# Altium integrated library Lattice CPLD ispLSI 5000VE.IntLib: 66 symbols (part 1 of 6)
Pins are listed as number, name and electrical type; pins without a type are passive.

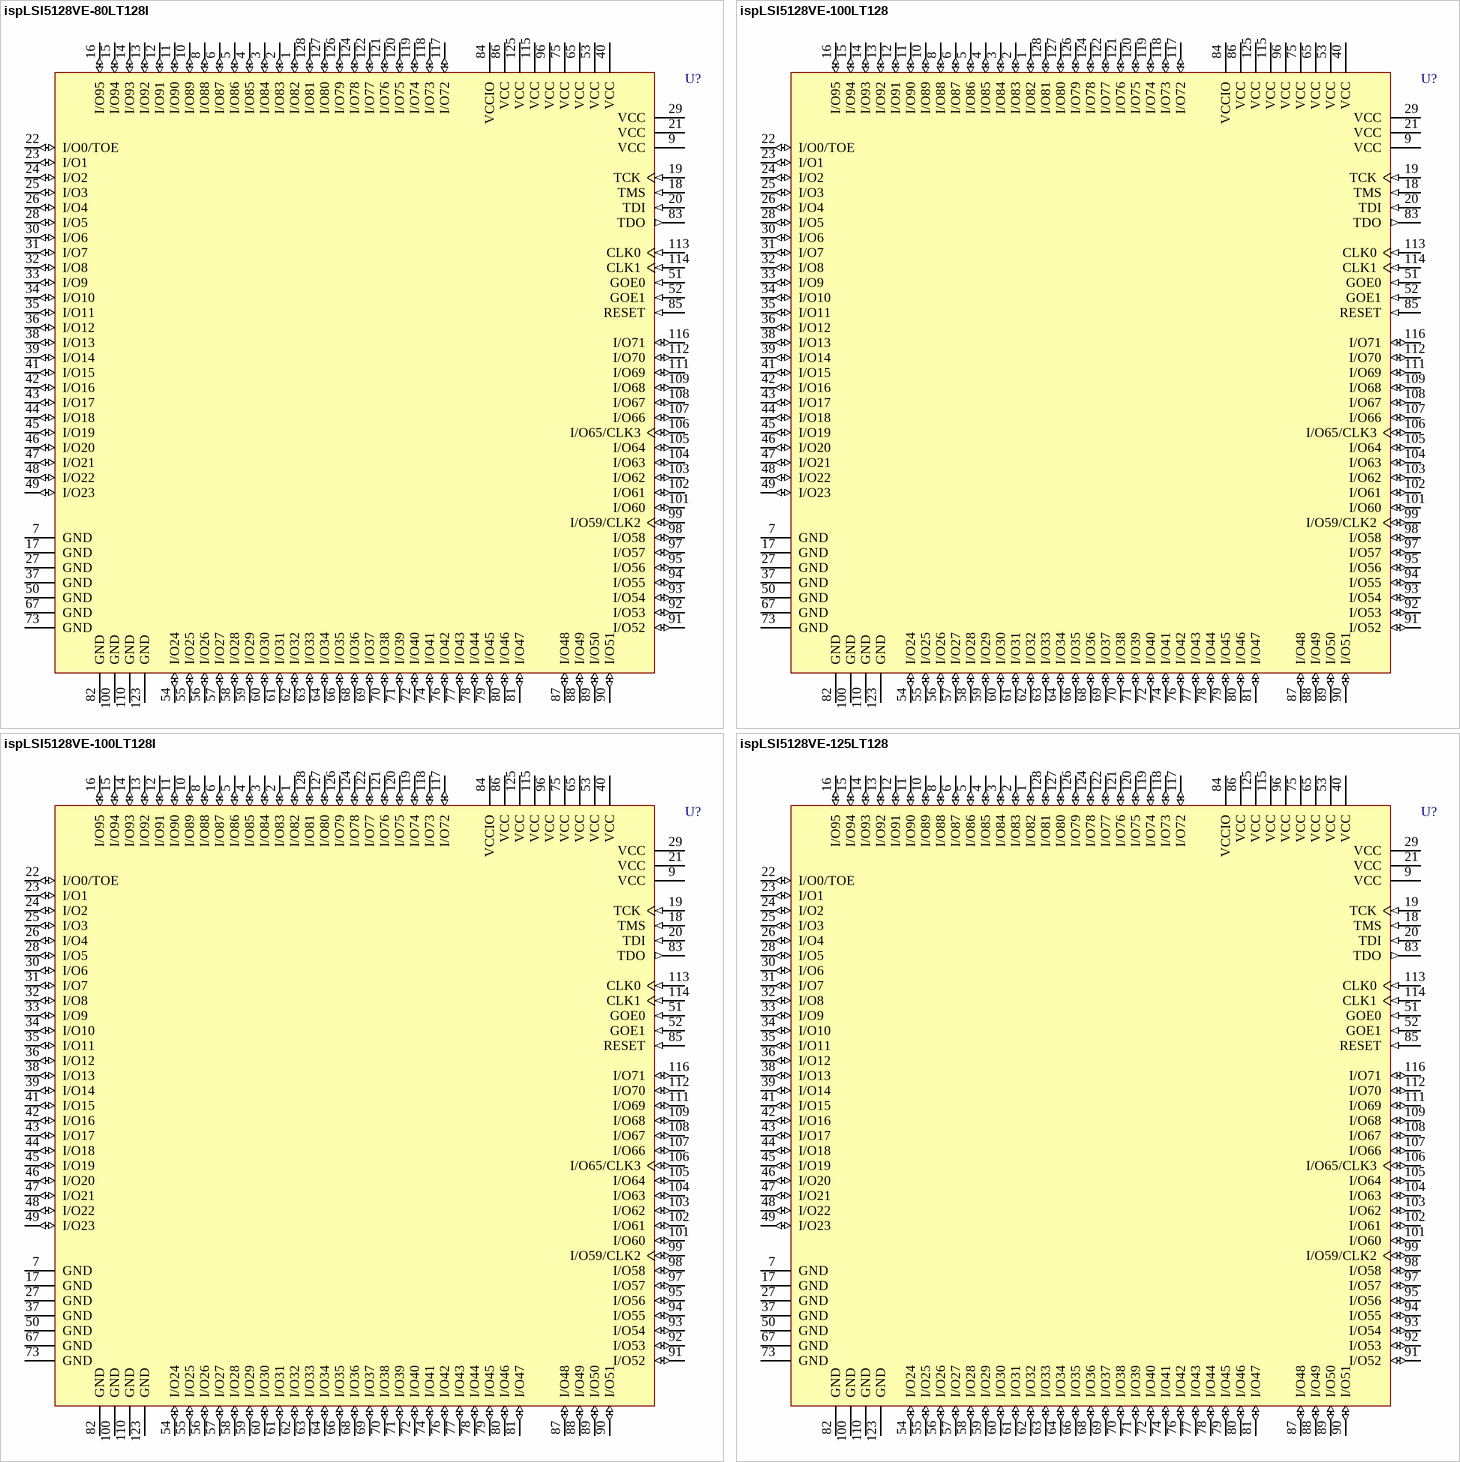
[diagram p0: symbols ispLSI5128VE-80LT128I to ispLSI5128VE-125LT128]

## ispLSI5128VE-80LT128I
designator U?
ispLSI 5128VE SuperWIDE High Density PLD with 96 User I/Os, 12 ns, 3.3 V, Industrial Grade
footprint TQFP128_N (Thin QFP, 128-Leads, Body 14x14mm, Pitch 0.4mm, IPC Medium Density)
footprint TQFP128_L (Thin QFP, 128-Leads, Body 14x14mm, Pitch 0.4mm, IPC High Density)
footprint TQFP128_M (Thin QFP, 128-Leads, Body 14x14mm, Pitch 0.4mm, IPC Low Density)
3D model 5128VE-TQFP128 (128-Pin Thin Quad Flat Pack 0.4 mm Pitch)
pins: 1 I/O82 (io), 2 I/O83 (io), 3 I/O84 (io), 4 I/O85 (io), 5 I/O86 (io), 6 I/O87 (io), 7 GND (power), 8 I/O88 (io), 9 VCC (power), 10 I/O89 (io), 11 I/O90 (io), 12 I/O91 (io), 13 I/O92 (io), 14 I/O93 (io), 15 I/O94 (io), 16 I/O95 (io), 17 GND (power), 18 TMS (in), 19 TCK (in), 20 TDI (in), 21 VCC (power), 22 I/O0/TOE (io), 23 I/O1 (io), 24 I/O2 (io), 25 I/O3 (io), 26 I/O4 (io), 27 GND (power), 28 I/O5 (io), 29 VCC (power), 30 I/O6 (io), 31 I/O7 (io), 32 I/O8 (io), 33 I/O9 (io), 34 I/O10 (io), 35 I/O11 (io), 36 I/O12 (io), 37 GND (power), 38 I/O13 (io), 39 I/O14 (io), 40 VCC (power), 41 I/O15 (io), 42 I/O16 (io), 43 I/O17 (io), 44 I/O18 (io), 45 I/O19 (io), 46 I/O20 (io), 47 I/O21 (io), 48 I/O22 (io), 49 I/O23 (io), 50 GND (power), 51 GOE0 (in), 52 GOE1 (in), 53 VCC (power), 54 I/O24 (io), 55 I/O25 (io), 56 I/O26 (io), 57 I/O27 (io), 58 I/O28 (io), 59 I/O29 (io), 60 I/O30 (io), 61 I/O31 (io), 62 I/O32 (io), 63 I/O33 (io), 64 I/O34 (io), 65 VCC (power), 66 I/O35 (io), 67 GND (power), 68 I/O36 (io), 69 I/O37 (io), 70 I/O38 (io), 71 I/O39 (io), 72 I/O40 (io), 73 GND (power), 74 I/O41 (io), 75 VCC (power), 76 I/O42 (io), 77 I/O43 (io), 78 I/O44 (io), 79 I/O45 (io), 80 I/O46 (io), 81 I/O47 (io), 82 GND (power), 83 TDO (out), 84 VCCIO (power), 85 RESET (in), 86 VCC (power), 87 I/O48 (io), 88 I/O49 (io), 89 I/O50 (io), 90 I/O51 (io), 91 I/O52 (io), 92 I/O53 (io), 93 I/O54 (io), 94 I/O55 (io), 95 I/O56 (io), 96 VCC (power), 97 I/O57 (io), 98 I/O58 (io), 99 I/O59/CLK2 (io), 100 GND (power), 101 I/O60 (io), 102 I/O61 (io), 103 I/O62 (io), 104 I/O63 (io), 105 I/O64 (io), 106 I/O65/CLK3 (io), 107 I/O66 (io), 108 I/O67 (io), 109 I/O68 (io), 110 GND (power), 111 I/O69 (io), 112 I/O70 (io), 113 CLK0 (in), 114 CLK1 (in), 115 VCC (power), 116 I/O71 (io), 117 I/O72 (io), 118 I/O73 (io), 119 I/O74 (io), 120 I/O75 (io), 121 I/O76 (io), 122 I/O77 (io), 123 GND (power), 124 I/O78 (io), 125 VCC (power), 126 I/O79 (io), 127 I/O80 (io), 128 I/O81 (io)

## ispLSI5128VE-100LT128
designator U?
ispLSI 5128VE SuperWIDE High Density PLD with 96 User I/Os, 10 ns, 3.3 V, Commercial Grade
footprint TQFP128_N (Thin QFP, 128-Leads, Body 14x14mm, Pitch 0.4mm, IPC Medium Density)
footprint TQFP128_L (Thin QFP, 128-Leads, Body 14x14mm, Pitch 0.4mm, IPC High Density)
footprint TQFP128_M (Thin QFP, 128-Leads, Body 14x14mm, Pitch 0.4mm, IPC Low Density)
3D model 5128VE-TQFP128 (128-Pin Thin Quad Flat Pack 0.4 mm Pitch)
pins: 1 I/O82 (io), 2 I/O83 (io), 3 I/O84 (io), 4 I/O85 (io), 5 I/O86 (io), 6 I/O87 (io), 7 GND (power), 8 I/O88 (io), 9 VCC (power), 10 I/O89 (io), 11 I/O90 (io), 12 I/O91 (io), 13 I/O92 (io), 14 I/O93 (io), 15 I/O94 (io), 16 I/O95 (io), 17 GND (power), 18 TMS (in), 19 TCK (in), 20 TDI (in), 21 VCC (power), 22 I/O0/TOE (io), 23 I/O1 (io), 24 I/O2 (io), 25 I/O3 (io), 26 I/O4 (io), 27 GND (power), 28 I/O5 (io), 29 VCC (power), 30 I/O6 (io), 31 I/O7 (io), 32 I/O8 (io), 33 I/O9 (io), 34 I/O10 (io), 35 I/O11 (io), 36 I/O12 (io), 37 GND (power), 38 I/O13 (io), 39 I/O14 (io), 40 VCC (power), 41 I/O15 (io), 42 I/O16 (io), 43 I/O17 (io), 44 I/O18 (io), 45 I/O19 (io), 46 I/O20 (io), 47 I/O21 (io), 48 I/O22 (io), 49 I/O23 (io), 50 GND (power), 51 GOE0 (in), 52 GOE1 (in), 53 VCC (power), 54 I/O24 (io), 55 I/O25 (io), 56 I/O26 (io), 57 I/O27 (io), 58 I/O28 (io), 59 I/O29 (io), 60 I/O30 (io), 61 I/O31 (io), 62 I/O32 (io), 63 I/O33 (io), 64 I/O34 (io), 65 VCC (power), 66 I/O35 (io), 67 GND (power), 68 I/O36 (io), 69 I/O37 (io), 70 I/O38 (io), 71 I/O39 (io), 72 I/O40 (io), 73 GND (power), 74 I/O41 (io), 75 VCC (power), 76 I/O42 (io), 77 I/O43 (io), 78 I/O44 (io), 79 I/O45 (io), 80 I/O46 (io), 81 I/O47 (io), 82 GND (power), 83 TDO (out), 84 VCCIO (power), 85 RESET (in), 86 VCC (power), 87 I/O48 (io), 88 I/O49 (io), 89 I/O50 (io), 90 I/O51 (io), 91 I/O52 (io), 92 I/O53 (io), 93 I/O54 (io), 94 I/O55 (io), 95 I/O56 (io), 96 VCC (power), 97 I/O57 (io), 98 I/O58 (io), 99 I/O59/CLK2 (io), 100 GND (power), 101 I/O60 (io), 102 I/O61 (io), 103 I/O62 (io), 104 I/O63 (io), 105 I/O64 (io), 106 I/O65/CLK3 (io), 107 I/O66 (io), 108 I/O67 (io), 109 I/O68 (io), 110 GND (power), 111 I/O69 (io), 112 I/O70 (io), 113 CLK0 (in), 114 CLK1 (in), 115 VCC (power), 116 I/O71 (io), 117 I/O72 (io), 118 I/O73 (io), 119 I/O74 (io), 120 I/O75 (io), 121 I/O76 (io), 122 I/O77 (io), 123 GND (power), 124 I/O78 (io), 125 VCC (power), 126 I/O79 (io), 127 I/O80 (io), 128 I/O81 (io)

## ispLSI5128VE-100LT128I
designator U?
ispLSI 5128VE SuperWIDE High Density PLD with 96 User I/Os, 10 ns, 3.3 V, Industrial Grade
footprint TQFP128_N (Thin QFP, 128-Leads, Body 14x14mm, Pitch 0.4mm, IPC Medium Density)
footprint TQFP128_L (Thin QFP, 128-Leads, Body 14x14mm, Pitch 0.4mm, IPC High Density)
footprint TQFP128_M (Thin QFP, 128-Leads, Body 14x14mm, Pitch 0.4mm, IPC Low Density)
3D model 5128VE-TQFP128 (128-Pin Thin Quad Flat Pack 0.4 mm Pitch)
pins: 1 I/O82 (io), 2 I/O83 (io), 3 I/O84 (io), 4 I/O85 (io), 5 I/O86 (io), 6 I/O87 (io), 7 GND (power), 8 I/O88 (io), 9 VCC (power), 10 I/O89 (io), 11 I/O90 (io), 12 I/O91 (io), 13 I/O92 (io), 14 I/O93 (io), 15 I/O94 (io), 16 I/O95 (io), 17 GND (power), 18 TMS (in), 19 TCK (in), 20 TDI (in), 21 VCC (power), 22 I/O0/TOE (io), 23 I/O1 (io), 24 I/O2 (io), 25 I/O3 (io), 26 I/O4 (io), 27 GND (power), 28 I/O5 (io), 29 VCC (power), 30 I/O6 (io), 31 I/O7 (io), 32 I/O8 (io), 33 I/O9 (io), 34 I/O10 (io), 35 I/O11 (io), 36 I/O12 (io), 37 GND (power), 38 I/O13 (io), 39 I/O14 (io), 40 VCC (power), 41 I/O15 (io), 42 I/O16 (io), 43 I/O17 (io), 44 I/O18 (io), 45 I/O19 (io), 46 I/O20 (io), 47 I/O21 (io), 48 I/O22 (io), 49 I/O23 (io), 50 GND (power), 51 GOE0 (in), 52 GOE1 (in), 53 VCC (power), 54 I/O24 (io), 55 I/O25 (io), 56 I/O26 (io), 57 I/O27 (io), 58 I/O28 (io), 59 I/O29 (io), 60 I/O30 (io), 61 I/O31 (io), 62 I/O32 (io), 63 I/O33 (io), 64 I/O34 (io), 65 VCC (power), 66 I/O35 (io), 67 GND (power), 68 I/O36 (io), 69 I/O37 (io), 70 I/O38 (io), 71 I/O39 (io), 72 I/O40 (io), 73 GND (power), 74 I/O41 (io), 75 VCC (power), 76 I/O42 (io), 77 I/O43 (io), 78 I/O44 (io), 79 I/O45 (io), 80 I/O46 (io), 81 I/O47 (io), 82 GND (power), 83 TDO (out), 84 VCCIO (power), 85 RESET (in), 86 VCC (power), 87 I/O48 (io), 88 I/O49 (io), 89 I/O50 (io), 90 I/O51 (io), 91 I/O52 (io), 92 I/O53 (io), 93 I/O54 (io), 94 I/O55 (io), 95 I/O56 (io), 96 VCC (power), 97 I/O57 (io), 98 I/O58 (io), 99 I/O59/CLK2 (io), 100 GND (power), 101 I/O60 (io), 102 I/O61 (io), 103 I/O62 (io), 104 I/O63 (io), 105 I/O64 (io), 106 I/O65/CLK3 (io), 107 I/O66 (io), 108 I/O67 (io), 109 I/O68 (io), 110 GND (power), 111 I/O69 (io), 112 I/O70 (io), 113 CLK0 (in), 114 CLK1 (in), 115 VCC (power), 116 I/O71 (io), 117 I/O72 (io), 118 I/O73 (io), 119 I/O74 (io), 120 I/O75 (io), 121 I/O76 (io), 122 I/O77 (io), 123 GND (power), 124 I/O78 (io), 125 VCC (power), 126 I/O79 (io), 127 I/O80 (io), 128 I/O81 (io)

## ispLSI5128VE-125LT128
designator U?
ispLSI 5128VE SuperWIDE High Density PLD with 96 User I/Os, 7.5 ns, 3.3 V, Commercial Grade
footprint TQFP128_N (Thin QFP, 128-Leads, Body 14x14mm, Pitch 0.4mm, IPC Medium Density)
footprint TQFP128_L (Thin QFP, 128-Leads, Body 14x14mm, Pitch 0.4mm, IPC High Density)
footprint TQFP128_M (Thin QFP, 128-Leads, Body 14x14mm, Pitch 0.4mm, IPC Low Density)
3D model 5128VE-TQFP128 (128-Pin Thin Quad Flat Pack 0.4 mm Pitch)
pins: 1 I/O82 (io), 2 I/O83 (io), 3 I/O84 (io), 4 I/O85 (io), 5 I/O86 (io), 6 I/O87 (io), 7 GND (power), 8 I/O88 (io), 9 VCC (power), 10 I/O89 (io), 11 I/O90 (io), 12 I/O91 (io), 13 I/O92 (io), 14 I/O93 (io), 15 I/O94 (io), 16 I/O95 (io), 17 GND (power), 18 TMS (in), 19 TCK (in), 20 TDI (in), 21 VCC (power), 22 I/O0/TOE (io), 23 I/O1 (io), 24 I/O2 (io), 25 I/O3 (io), 26 I/O4 (io), 27 GND (power), 28 I/O5 (io), 29 VCC (power), 30 I/O6 (io), 31 I/O7 (io), 32 I/O8 (io), 33 I/O9 (io), 34 I/O10 (io), 35 I/O11 (io), 36 I/O12 (io), 37 GND (power), 38 I/O13 (io), 39 I/O14 (io), 40 VCC (power), 41 I/O15 (io), 42 I/O16 (io), 43 I/O17 (io), 44 I/O18 (io), 45 I/O19 (io), 46 I/O20 (io), 47 I/O21 (io), 48 I/O22 (io), 49 I/O23 (io), 50 GND (power), 51 GOE0 (in), 52 GOE1 (in), 53 VCC (power), 54 I/O24 (io), 55 I/O25 (io), 56 I/O26 (io), 57 I/O27 (io), 58 I/O28 (io), 59 I/O29 (io), 60 I/O30 (io), 61 I/O31 (io), 62 I/O32 (io), 63 I/O33 (io), 64 I/O34 (io), 65 VCC (power), 66 I/O35 (io), 67 GND (power), 68 I/O36 (io), 69 I/O37 (io), 70 I/O38 (io), 71 I/O39 (io), 72 I/O40 (io), 73 GND (power), 74 I/O41 (io), 75 VCC (power), 76 I/O42 (io), 77 I/O43 (io), 78 I/O44 (io), 79 I/O45 (io), 80 I/O46 (io), 81 I/O47 (io), 82 GND (power), 83 TDO (out), 84 VCCIO (power), 85 RESET (in), 86 VCC (power), 87 I/O48 (io), 88 I/O49 (io), 89 I/O50 (io), 90 I/O51 (io), 91 I/O52 (io), 92 I/O53 (io), 93 I/O54 (io), 94 I/O55 (io), 95 I/O56 (io), 96 VCC (power), 97 I/O57 (io), 98 I/O58 (io), 99 I/O59/CLK2 (io), 100 GND (power), 101 I/O60 (io), 102 I/O61 (io), 103 I/O62 (io), 104 I/O63 (io), 105 I/O64 (io), 106 I/O65/CLK3 (io), 107 I/O66 (io), 108 I/O67 (io), 109 I/O68 (io), 110 GND (power), 111 I/O69 (io), 112 I/O70 (io), 113 CLK0 (in), 114 CLK1 (in), 115 VCC (power), 116 I/O71 (io), 117 I/O72 (io), 118 I/O73 (io), 119 I/O74 (io), 120 I/O75 (io), 121 I/O76 (io), 122 I/O77 (io), 123 GND (power), 124 I/O78 (io), 125 VCC (power), 126 I/O79 (io), 127 I/O80 (io), 128 I/O81 (io)

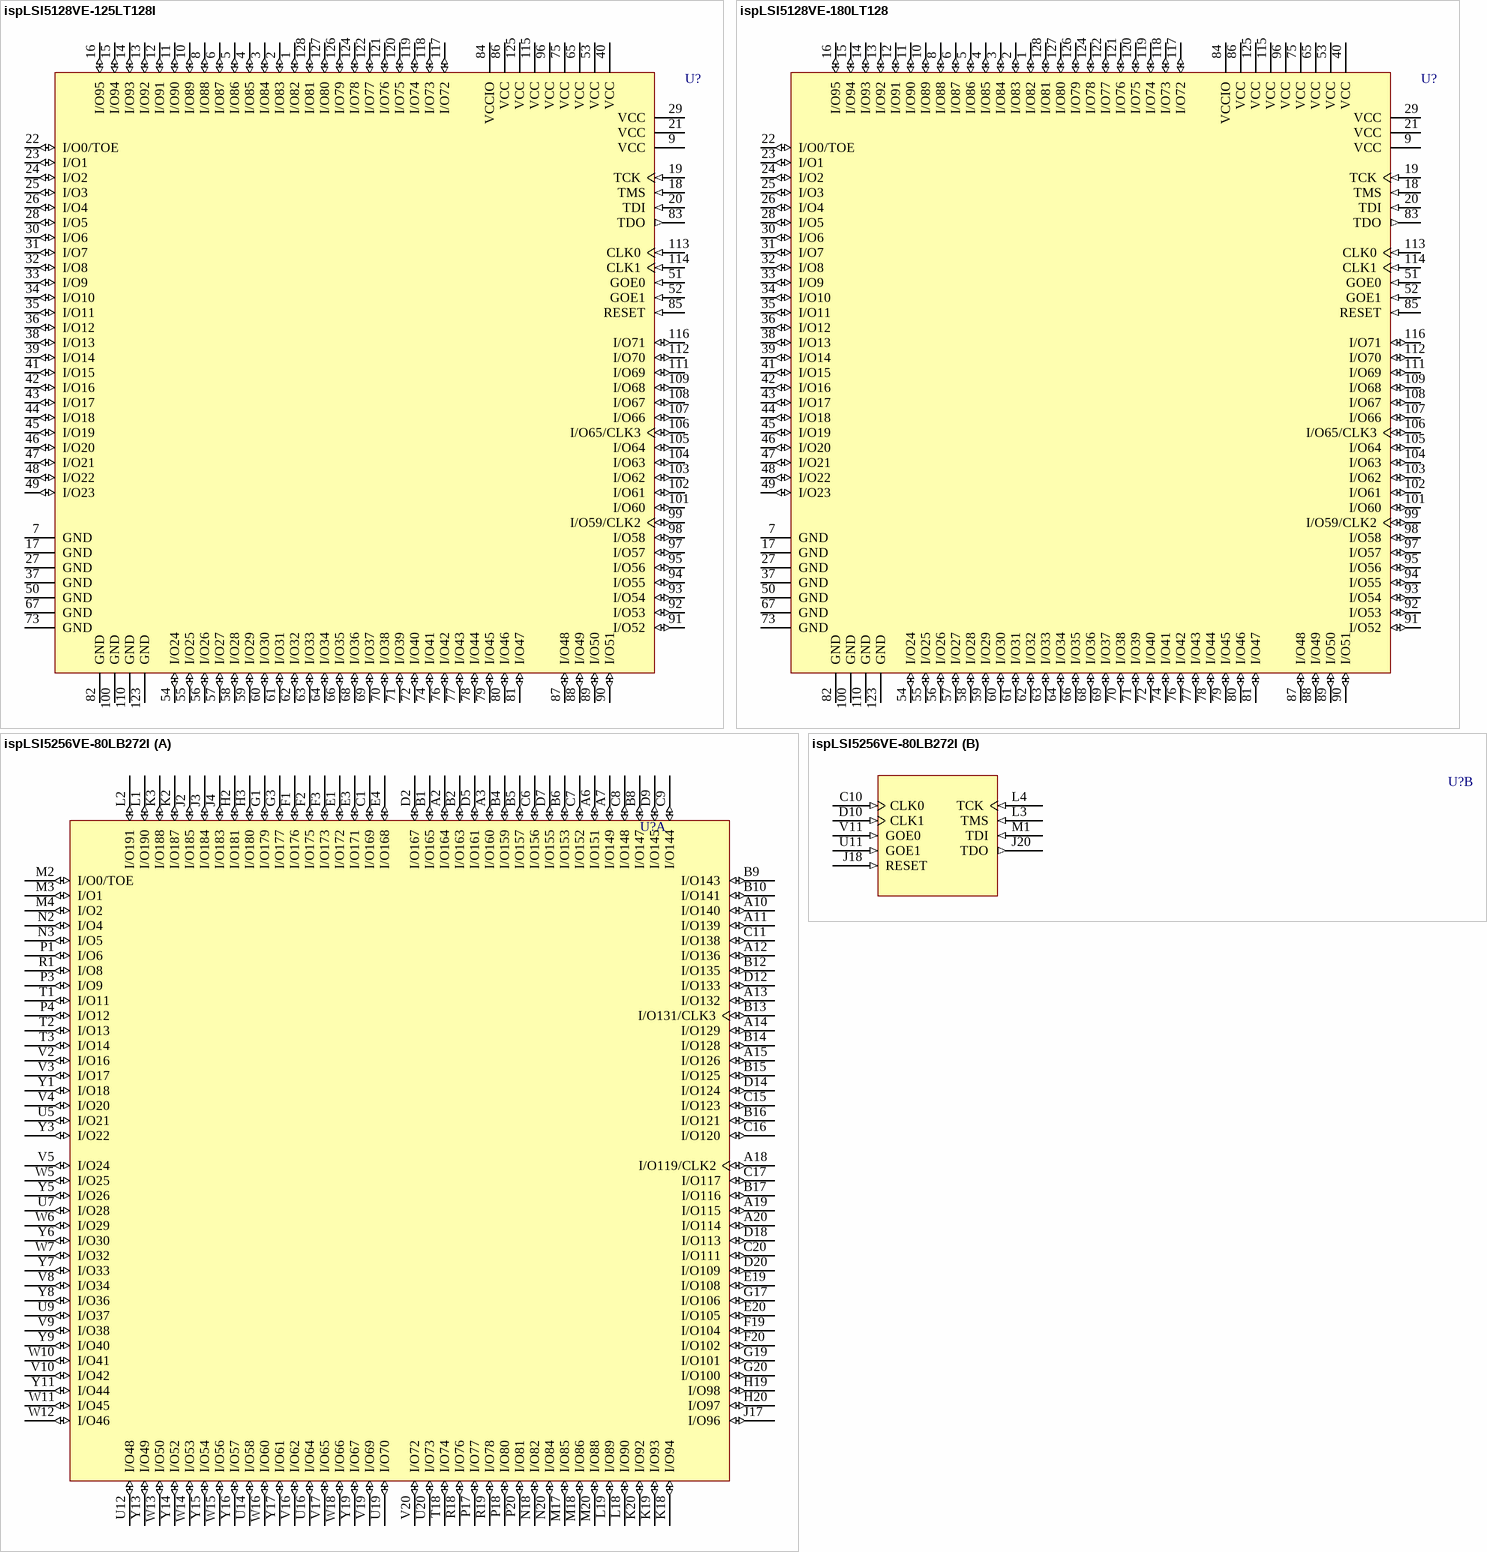
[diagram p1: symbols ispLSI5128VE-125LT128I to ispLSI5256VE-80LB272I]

## ispLSI5128VE-125LT128I
designator U?
ispLSI 5128VE SuperWIDE High Density PLD with 96 User I/Os, 7.5 ns, 3.3 V, Industrial Grade
footprint TQFP128_N (Thin QFP, 128-Leads, Body 14x14mm, Pitch 0.4mm, IPC Medium Density)
footprint TQFP128_L (Thin QFP, 128-Leads, Body 14x14mm, Pitch 0.4mm, IPC High Density)
footprint TQFP128_M (Thin QFP, 128-Leads, Body 14x14mm, Pitch 0.4mm, IPC Low Density)
3D model 5128VE-TQFP128 (128-Pin Thin Quad Flat Pack 0.4 mm Pitch)
pins: 1 I/O82 (io), 2 I/O83 (io), 3 I/O84 (io), 4 I/O85 (io), 5 I/O86 (io), 6 I/O87 (io), 7 GND (power), 8 I/O88 (io), 9 VCC (power), 10 I/O89 (io), 11 I/O90 (io), 12 I/O91 (io), 13 I/O92 (io), 14 I/O93 (io), 15 I/O94 (io), 16 I/O95 (io), 17 GND (power), 18 TMS (in), 19 TCK (in), 20 TDI (in), 21 VCC (power), 22 I/O0/TOE (io), 23 I/O1 (io), 24 I/O2 (io), 25 I/O3 (io), 26 I/O4 (io), 27 GND (power), 28 I/O5 (io), 29 VCC (power), 30 I/O6 (io), 31 I/O7 (io), 32 I/O8 (io), 33 I/O9 (io), 34 I/O10 (io), 35 I/O11 (io), 36 I/O12 (io), 37 GND (power), 38 I/O13 (io), 39 I/O14 (io), 40 VCC (power), 41 I/O15 (io), 42 I/O16 (io), 43 I/O17 (io), 44 I/O18 (io), 45 I/O19 (io), 46 I/O20 (io), 47 I/O21 (io), 48 I/O22 (io), 49 I/O23 (io), 50 GND (power), 51 GOE0 (in), 52 GOE1 (in), 53 VCC (power), 54 I/O24 (io), 55 I/O25 (io), 56 I/O26 (io), 57 I/O27 (io), 58 I/O28 (io), 59 I/O29 (io), 60 I/O30 (io), 61 I/O31 (io), 62 I/O32 (io), 63 I/O33 (io), 64 I/O34 (io), 65 VCC (power), 66 I/O35 (io), 67 GND (power), 68 I/O36 (io), 69 I/O37 (io), 70 I/O38 (io), 71 I/O39 (io), 72 I/O40 (io), 73 GND (power), 74 I/O41 (io), 75 VCC (power), 76 I/O42 (io), 77 I/O43 (io), 78 I/O44 (io), 79 I/O45 (io), 80 I/O46 (io), 81 I/O47 (io), 82 GND (power), 83 TDO (out), 84 VCCIO (power), 85 RESET (in), 86 VCC (power), 87 I/O48 (io), 88 I/O49 (io), 89 I/O50 (io), 90 I/O51 (io), 91 I/O52 (io), 92 I/O53 (io), 93 I/O54 (io), 94 I/O55 (io), 95 I/O56 (io), 96 VCC (power), 97 I/O57 (io), 98 I/O58 (io), 99 I/O59/CLK2 (io), 100 GND (power), 101 I/O60 (io), 102 I/O61 (io), 103 I/O62 (io), 104 I/O63 (io), 105 I/O64 (io), 106 I/O65/CLK3 (io), 107 I/O66 (io), 108 I/O67 (io), 109 I/O68 (io), 110 GND (power), 111 I/O69 (io), 112 I/O70 (io), 113 CLK0 (in), 114 CLK1 (in), 115 VCC (power), 116 I/O71 (io), 117 I/O72 (io), 118 I/O73 (io), 119 I/O74 (io), 120 I/O75 (io), 121 I/O76 (io), 122 I/O77 (io), 123 GND (power), 124 I/O78 (io), 125 VCC (power), 126 I/O79 (io), 127 I/O80 (io), 128 I/O81 (io)

## ispLSI5128VE-180LT128
designator U?
ispLSI 5128VE SuperWIDE High Density PLD with 96 User I/Os, 5.0 ns, 3.3 V, Commercial Grade
footprint TQFP128_N (Thin QFP, 128-Leads, Body 14x14mm, Pitch 0.4mm, IPC Medium Density)
footprint TQFP128_L (Thin QFP, 128-Leads, Body 14x14mm, Pitch 0.4mm, IPC High Density)
footprint TQFP128_M (Thin QFP, 128-Leads, Body 14x14mm, Pitch 0.4mm, IPC Low Density)
3D model 5128VE-TQFP128 (128-Pin Thin Quad Flat Pack 0.4 mm Pitch)
pins: 1 I/O82 (io), 2 I/O83 (io), 3 I/O84 (io), 4 I/O85 (io), 5 I/O86 (io), 6 I/O87 (io), 7 GND (power), 8 I/O88 (io), 9 VCC (power), 10 I/O89 (io), 11 I/O90 (io), 12 I/O91 (io), 13 I/O92 (io), 14 I/O93 (io), 15 I/O94 (io), 16 I/O95 (io), 17 GND (power), 18 TMS (in), 19 TCK (in), 20 TDI (in), 21 VCC (power), 22 I/O0/TOE (io), 23 I/O1 (io), 24 I/O2 (io), 25 I/O3 (io), 26 I/O4 (io), 27 GND (power), 28 I/O5 (io), 29 VCC (power), 30 I/O6 (io), 31 I/O7 (io), 32 I/O8 (io), 33 I/O9 (io), 34 I/O10 (io), 35 I/O11 (io), 36 I/O12 (io), 37 GND (power), 38 I/O13 (io), 39 I/O14 (io), 40 VCC (power), 41 I/O15 (io), 42 I/O16 (io), 43 I/O17 (io), 44 I/O18 (io), 45 I/O19 (io), 46 I/O20 (io), 47 I/O21 (io), 48 I/O22 (io), 49 I/O23 (io), 50 GND (power), 51 GOE0 (in), 52 GOE1 (in), 53 VCC (power), 54 I/O24 (io), 55 I/O25 (io), 56 I/O26 (io), 57 I/O27 (io), 58 I/O28 (io), 59 I/O29 (io), 60 I/O30 (io), 61 I/O31 (io), 62 I/O32 (io), 63 I/O33 (io), 64 I/O34 (io), 65 VCC (power), 66 I/O35 (io), 67 GND (power), 68 I/O36 (io), 69 I/O37 (io), 70 I/O38 (io), 71 I/O39 (io), 72 I/O40 (io), 73 GND (power), 74 I/O41 (io), 75 VCC (power), 76 I/O42 (io), 77 I/O43 (io), 78 I/O44 (io), 79 I/O45 (io), 80 I/O46 (io), 81 I/O47 (io), 82 GND (power), 83 TDO (out), 84 VCCIO (power), 85 RESET (in), 86 VCC (power), 87 I/O48 (io), 88 I/O49 (io), 89 I/O50 (io), 90 I/O51 (io), 91 I/O52 (io), 92 I/O53 (io), 93 I/O54 (io), 94 I/O55 (io), 95 I/O56 (io), 96 VCC (power), 97 I/O57 (io), 98 I/O58 (io), 99 I/O59/CLK2 (io), 100 GND (power), 101 I/O60 (io), 102 I/O61 (io), 103 I/O62 (io), 104 I/O63 (io), 105 I/O64 (io), 106 I/O65/CLK3 (io), 107 I/O66 (io), 108 I/O67 (io), 109 I/O68 (io), 110 GND (power), 111 I/O69 (io), 112 I/O70 (io), 113 CLK0 (in), 114 CLK1 (in), 115 VCC (power), 116 I/O71 (io), 117 I/O72 (io), 118 I/O73 (io), 119 I/O74 (io), 120 I/O75 (io), 121 I/O76 (io), 122 I/O77 (io), 123 GND (power), 124 I/O78 (io), 125 VCC (power), 126 I/O79 (io), 127 I/O80 (io), 128 I/O81 (io)

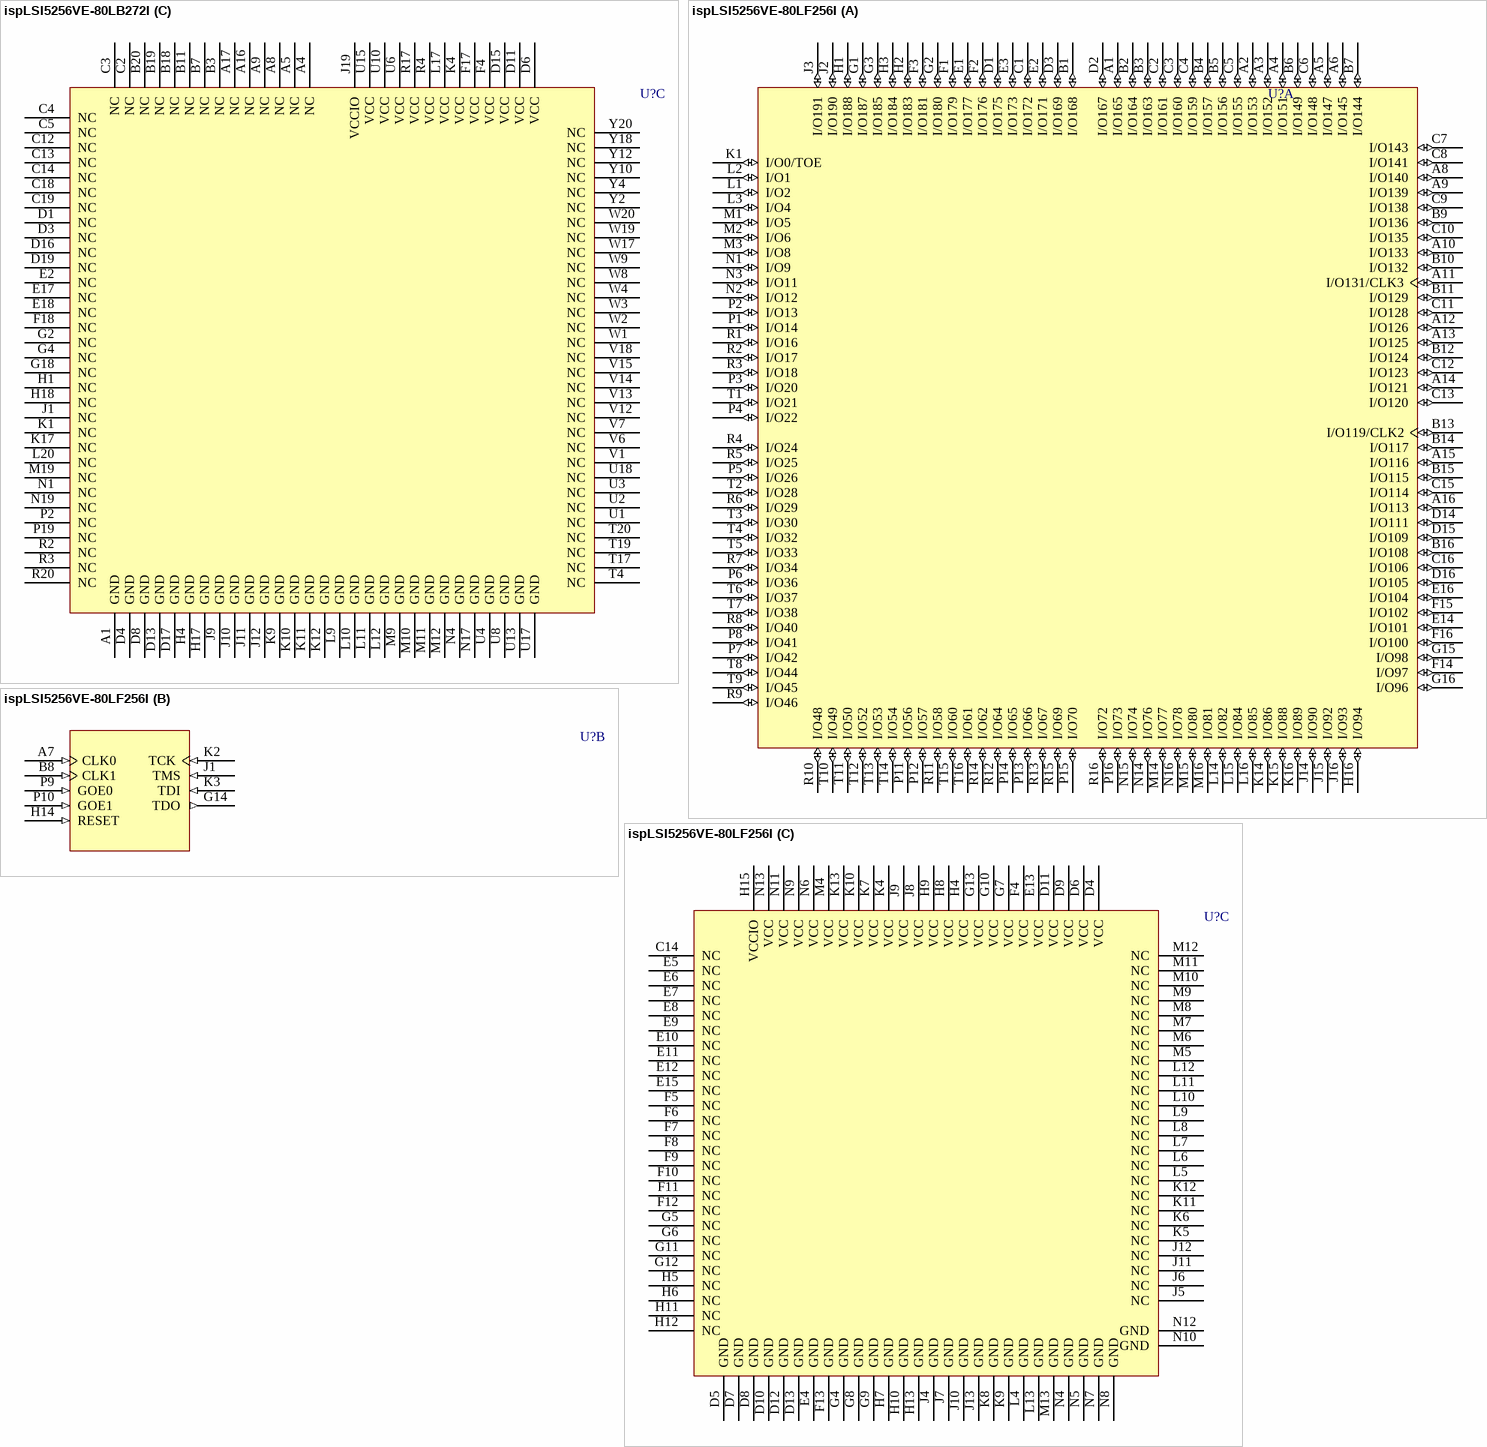
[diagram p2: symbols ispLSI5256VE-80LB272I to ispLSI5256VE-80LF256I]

## ispLSI5256VE-80LB272I
designator U?
ispLSI 5256VE SuperWIDE High Density PLD with 144 User I/Os, 12 ns, 3.3 V, Industrial Grade
footprint BGA272 (BGA, 272-Leads, Body 27x27mm, Pitch 1.27mm)
3D model 5256VE-BGA272 (272-Ball Ball Grid Array (BGA272))
part A pins: A2 I/O164 (io), A3 I/O160 (io), A6 I/O151 (io), A7 I/O149 (io), A10 I/O140 (io), A11 I/O139 (io), A12 I/O136 (io), A13 I/O132 (io), A14 I/O129 (io), A15 I/O126 (io), A18 I/O119/CLK2 (io), A19 I/O115 (io), A20 I/O114 (io), B1 I/O165 (io), B2 I/O163 (io), B4 I/O159 (io), B5 I/O157 (io), B6 I/O153 (io), B8 I/O147 (io), B9 I/O143 (io), B10 I/O141 (io), B12 I/O135 (io), B13 I/O131/CLK3 (io), B14 I/O128 (io), B15 I/O125 (io), B16 I/O121 (io), B17 I/O116 (io), C1 I/O169 (io), C6 I/O156 (io), C7 I/O152 (io), C8 I/O148 (io), C9 I/O144 (io), C11 I/O138 (io), C15 I/O123 (io), C16 I/O120 (io), C17 I/O117 (io), C20 I/O111 (io), D2 I/O167 (io), D5 I/O161 (io), D7 I/O155 (io), D9 I/O145 (io), D12 I/O133 (io), D14 I/O124 (io), D18 I/O113 (io), D20 I/O109 (io), E1 I/O172 (io), E3 I/O171 (io), E4 I/O168 (io), E19 I/O108 (io), E20 I/O105 (io), F1 I/O176 (io), F2 I/O175 (io), F3 I/O173 (io), F19 I/O104 (io), F20 I/O102 (io), G1 I/O179 (io), G3 I/O177 (io), G17 I/O106 (io), G19 I/O101 (io), G20 I/O100 (io), H2 I/O181 (io), H3 I/O180 (io), H19 I/O98 (io), H20 I/O97 (io), J2 I/O185 (io), J3 I/O184 (io), J4 I/O183 (io), J17 I/O96 (io), K2 I/O187 (io), K3 I/O188 (io), K18 I/O94 (io), K19 I/O93 (io), K20 I/O92 (io), L1 I/O190 (io), L2 I/O191 (io), L18 I/O90 (io), L19 I/O89 (io), M2 I/O0/TOE (io), M3 I/O1 (io), M4 I/O2 (io), M17 I/O85 (io), M18 I/O86 (io), M20 I/O88 (io), N2 I/O4 (io), N3 I/O5 (io), N18 I/O82 (io), N20 I/O84 (io), P1 I/O6 (io), P3 I/O9 (io), P4 I/O12 (io), P17 I/O77 (io), P18 I/O80 (io), P20 I/O81 (io), R1 I/O8 (io), R18 I/O76 (io), R19 I/O78 (io), T1 I/O11 (io), T2 I/O13 (io), T3 I/O14 (io), T18 I/O74 (io), U5 I/O21 (io), U7 I/O28 (io), U9 I/O37 (io), U12 I/O48 (io), U14 I/O58 (io), U16 I/O64 (io), U19 I/O70 (io), U20 I/O73 (io), V2 I/O16 (io), V3 I/O17 (io), V4 I/O20 (io), V5 I/O24 (io), V8 I/O34 (io), V9 I/O38 (io), V10 I/O42 (io), V16 I/O62 (io), V17 I/O65 (io), V19 I/O69 (io), V20 I/O72 (io), W5 I/O25 (io), W6 I/O29 (io), W7 I/O32 (io), W10 I/O41 (io), W11 I/O45 (io), W12 I/O46 (io), W13 I/O50 (io), W14 I/O53 (io), W15 I/O56 (io), W16 I/O60 (io), W18 I/O66 (io), Y1 I/O18 (io), Y3 I/O22 (io), Y5 I/O26 (io), Y6 I/O30 (io), Y7 I/O33 (io), Y8 I/O36 (io), Y9 I/O40 (io), Y11 I/O44 (io), Y13 I/O49 (io), Y14 I/O52 (io), Y15 I/O54 (io), Y16 I/O57 (io), Y17 I/O61 (io), Y19 I/O67 (io)
part B pins: C10 CLK0 (in), D10 CLK1 (in), J18 RESET (in), J20 TDO (out), L3 TMS (in), L4 TCK (in), M1 TDI (in), U11 GOE1 (in), V11 GOE0 (in)
part C pins: A1 GND (power), A4 NC, A5 NC, A8 NC, A9 NC, A16 NC, A17 NC, B3 NC, B7 NC, B11 NC, B18 NC, B19 NC, B20 NC, C2 NC, C3 NC, C4 NC, C5 NC, C12 NC, C13 NC, C14 NC, C18 NC, C19 NC, D1 NC, D3 NC, D4 GND (power), D6 VCC (power), D8 GND (power), D11 VCC (power), D13 GND (power), D15 VCC (power), D16 NC, D17 GND (power), D19 NC, E2 NC, E17 NC, E18 NC, F4 VCC (power), F17 VCC (power), F18 NC, G2 NC, G4 NC, G18 NC, H1 NC, H4 GND (power), H17 GND (power), H18 NC, J1 NC, J9 GND (power), J10 GND (power), J11 GND (power), J12 GND (power), J19 VCCIO (power), K1 NC, K4 VCC (power), K9 GND (power), K10 GND (power), K11 GND (power), K12 GND (power), K17 NC, L9 GND (power), L10 GND (power), L11 GND (power), L12 GND (power), L17 VCC (power), L20 NC, M9 GND (power), M10 GND (power), M11 GND (power), M12 GND (power), M19 NC, N1 NC, N4 GND (power), N17 GND (power), N19 NC, P2 NC, P19 NC, R2 NC, R3 NC, R4 VCC (power), R17 VCC (power), R20 NC, T4 NC, T17 NC, T19 NC, T20 NC, U1 NC, U2 NC, U3 NC, U4 GND (power), U6 VCC (power), U8 GND (power), U10 VCC (power), U13 GND (power), U15 VCC (power), U17 GND (power), U18 NC, V1 NC, V6 NC, V7 NC, V12 NC, V13 NC, V14 NC, V15 NC, V18 NC, W1 NC, W2 NC, W3 NC, W4 NC, W8 NC, W9 NC, W17 NC, W19 NC, W20 NC, Y2 NC, Y4 NC, Y10 NC, Y12 NC, Y18 NC, Y20 NC

## ispLSI5256VE-80LF256I
designator U?
ispLSI 5256VE SuperWIDE High Density PLD with 144 User I/Os, 12 ns, 3.3 V, Industrial Grade
footprint fpBGA256 (BGA, 256-Leads, Body 17x17mm, Pitch 1mm)
3D model 5256VE-fpBGA256 (256-Ball Fine Pitch Ball Grid Array (fpBGA256))
part A pins: A1 I/O165 (io), A2 I/O153 (io), A3 I/O152 (io), A4 I/O151 (io), A5 I/O147 (io), A6 I/O145 (io), A8 I/O140 (io), A9 I/O139 (io), A10 I/O133 (io), A11 I/O131/CLK3 (io), A12 I/O126 (io), A13 I/O125 (io), A14 I/O121 (io), A15 I/O116 (io), A16 I/O113 (io), B1 I/O168 (io), B2 I/O164 (io), B3 I/O163 (io), B4 I/O157 (io), B5 I/O156 (io), B6 I/O149 (io), B7 I/O144 (io), B9 I/O136 (io), B10 I/O132 (io), B11 I/O129 (io), B12 I/O124 (io), B13 I/O119/CLK2 (io), B14 I/O117 (io), B15 I/O115 (io), B16 I/O108 (io), C1 I/O172 (io), C2 I/O161 (io), C3 I/O160 (io), C4 I/O159 (io), C5 I/O155 (io), C6 I/O148 (io), C7 I/O143 (io), C8 I/O141 (io), C9 I/O138 (io), C10 I/O135 (io), C11 I/O128 (io), C12 I/O123 (io), C13 I/O120 (io), C15 I/O114 (io), C16 I/O106 (io), D1 I/O175 (io), D2 I/O167 (io), D3 I/O169 (io), D14 I/O111 (io), D15 I/O109 (io), D16 I/O105 (io), E1 I/O177 (io), E2 I/O171 (io), E3 I/O173 (io), E14 I/O101 (io), E16 I/O104 (io), F1 I/O179 (io), F2 I/O176 (io), F3 I/O181 (io), F14 I/O97 (io), F15 I/O102 (io), F16 I/O100 (io), G1 I/O187 (io), G2 I/O180 (io), G3 I/O185 (io), G15 I/O98 (io), G16 I/O96 (io), H1 I/O188 (io), H2 I/O183 (io), H3 I/O184 (io), H16 I/O94 (io), J2 I/O190 (io), J3 I/O191 (io), J14 I/O90 (io), J15 I/O92 (io), J16 I/O93 (io), K1 I/O0/TOE (io), K14 I/O86 (io), K15 I/O88 (io), K16 I/O89 (io), L1 I/O2 (io), L2 I/O1 (io), L3 I/O4 (io), L14 I/O82 (io), L15 I/O84 (io), L16 I/O85 (io), M1 I/O5 (io), M2 I/O6 (io), M3 I/O8 (io), M14 I/O77 (io), M15 I/O80 (io), M16 I/O81 (io), N1 I/O9 (io), N2 I/O12 (io), N3 I/O11 (io), N14 I/O76 (io), N15 I/O74 (io), N16 I/O78 (io), P1 I/O14 (io), P2 I/O13 (io), P3 I/O20 (io), P4 I/O22 (io), P5 I/O26 (io), P6 I/O36 (io), P7 I/O42 (io), P8 I/O41 (io), P11 I/O56 (io), P12 I/O57 (io), P13 I/O66 (io), P14 I/O65 (io), P15 I/O70 (io), P16 I/O73 (io), R1 I/O16 (io), R2 I/O17 (io), R3 I/O18 (io), R4 I/O24 (io), R5 I/O25 (io), R6 I/O29 (io), R7 I/O34 (io), R8 I/O40 (io), R9 I/O46 (io), R10 I/O48 (io), R11 I/O58 (io), R12 I/O64 (io), R13 I/O67 (io), R14 I/O62 (io), R15 I/O69 (io), R16 I/O72 (io), T1 I/O21 (io), T2 I/O28 (io), T3 I/O30 (io), T4 I/O32 (io), T5 I/O33 (io), T6 I/O37 (io), T7 I/O38 (io), T8 I/O44 (io), T9 I/O45 (io), T10 I/O49 (io), T11 I/O50 (io), T12 I/O52 (io), T13 I/O53 (io), T14 I/O54 (io), T15 I/O60 (io), T16 I/O61 (io)
part B pins: A7 CLK0 (in), B8 CLK1 (in), G14 TDO (out), H14 RESET (in), J1 TMS (in), K2 TCK (in), K3 TDI (in), P9 GOE0 (in), P10 GOE1 (in)
part C pins: C14 NC, D4 VCC (power), D5 GND (power), D6 VCC (power), D7 GND (power), D8 GND (power), D9 VCC (power), D10 GND (power), D11 VCC (power), D12 GND (power), D13 GND (power), E4 GND (power), E5 NC, E6 NC, E7 NC, E8 NC, E9 NC, E10 NC, E11 NC, E12 NC, E13 VCC (power), E15 NC, F4 VCC (power), F5 NC, F6 NC, F7 NC, F8 NC, F9 NC, F10 NC, F11 NC, F12 NC, F13 GND (power), G4 GND (power), G5 NC, G6 NC, G7 VCC (power), G8 GND (power), G9 GND (power), G10 VCC (power), G11 NC, G12 NC, G13 VCC (power), H4 VCC (power), H5 NC, H6 NC, H7 GND (power), H8 VCC (power), H9 VCC (power), H10 GND (power), H11 NC, H12 NC, H13 GND (power), H15 VCCIO (power), J4 GND (power), J5 NC, J6 NC, J7 GND (power), J8 VCC (power), J9 VCC (power), J10 GND (power), J11 NC, J12 NC, J13 GND (power), K4 VCC (power), K5 NC, K6 NC, K7 VCC (power), K8 GND (power), K9 GND (power), K10 VCC (power), K11 NC, K12 NC, K13 VCC (power), L4 GND (power), L5 NC, L6 NC, L7 NC, L8 NC, L9 NC, L10 NC, L11 NC, L12 NC, L13 GND (power), M4 VCC (power), M5 NC, M6 NC, M7 NC, M8 NC, M9 NC, M10 NC, M11 NC, M12 NC, M13 GND (power), N4 GND (power), N5 GND (power), N6 VCC (power), N7 GND (power), N8 GND (power), N9 VCC (power), N10 GND (power), N11 VCC (power), N12 GND (power), N13 VCC (power)

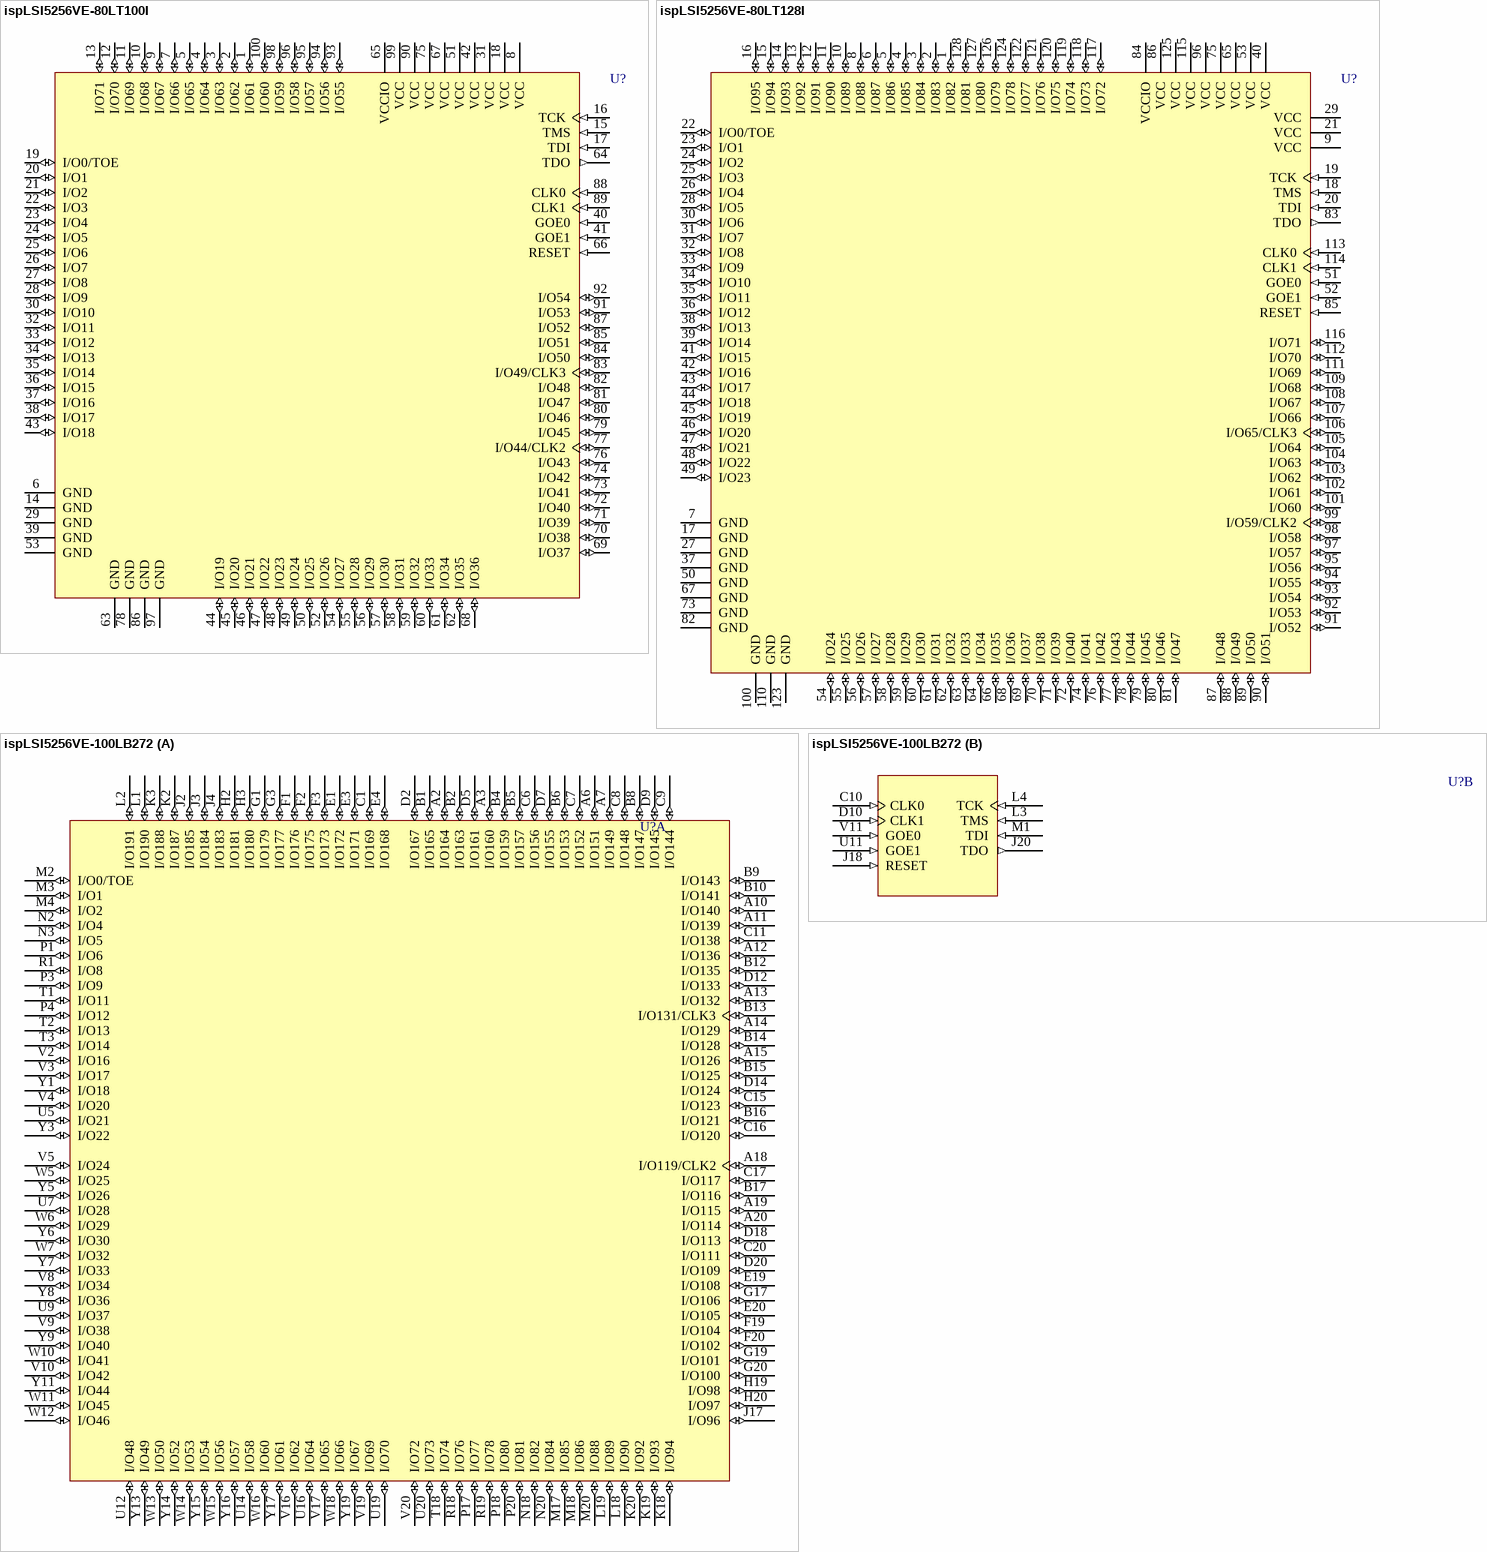
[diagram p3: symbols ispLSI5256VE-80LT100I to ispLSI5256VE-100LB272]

## ispLSI5256VE-80LT100I
designator U?
ispLSI 5256VE SuperWIDE High Density PLD with 72 User I/Os, 12 ns, 3.3 V, Industrial Grade
footprint TQFP100_N (Thin QFP, 100-Leads, Body 14x14mm, Pitch 0.5mm, IPC Medium Density)
footprint TQFP100_L (Thin QFP, 100-Leads, Body 14x14mm, Pitch 0.5mm, IPC High Density)
footprint TQFP100_M (Thin QFP, 100-Leads, Body 14x14mm, Pitch 0.5mm, IPC Low Density)
3D model 5256VE-TQFP100 (100-Pin Thin Quad Flat Pack (TQFP100))
pins: 1 I/O61 (io), 2 I/O62 (io), 3 I/O63 (io), 4 I/O64 (io), 5 I/O65 (io), 6 GND (power), 7 I/O66 (io), 8 VCC (power), 9 I/O67 (io), 10 I/O68 (io), 11 I/O69 (io), 12 I/O70 (io), 13 I/O71 (io), 14 GND (power), 15 TMS (in), 16 TCK (in), 17 TDI (in), 18 VCC (power), 19 I/O0/TOE (io), 20 I/O1 (io), 21 I/O2 (io), 22 I/O3 (io), 23 I/O4 (io), 24 I/O5 (io), 25 I/O6 (io), 26 I/O7 (io), 27 I/O8 (io), 28 I/O9 (io), 29 GND (power), 30 I/O10 (io), 31 VCC (power), 32 I/O11 (io), 33 I/O12 (io), 34 I/O13 (io), 35 I/O14 (io), 36 I/O15 (io), 37 I/O16 (io), 38 I/O17 (io), 39 GND (power), 40 GOE0 (in), 41 GOE1 (in), 42 VCC (power), 43 I/O18 (io), 44 I/O19 (io), 45 I/O20 (io), 46 I/O21 (io), 47 I/O22 (io), 48 I/O23 (io), 49 I/O24 (io), 50 I/O25 (io), 51 VCC (power), 52 I/O26 (io), 53 GND (power), 54 I/O27 (io), 55 I/O28 (io), 56 I/O29 (io), 57 I/O30 (io), 58 I/O31 (io), 59 I/O32 (io), 60 I/O33 (io), 61 I/O34 (io), 62 I/O35 (io), 63 GND (power), 64 TDO (out), 65 VCCIO (power), 66 RESET (in), 67 VCC (power), 68 I/O36 (io), 69 I/O37 (io), 70 I/O38 (io), 71 I/O39 (io), 72 I/O40 (io), 73 I/O41 (io), 74 I/O42 (io), 75 VCC (power), 76 I/O43 (io), 77 I/O44/CLK2 (io), 78 GND (power), 79 I/O45 (io), 80 I/O46 (io), 81 I/O47 (io), 82 I/O48 (io), 83 I/O49/CLK3 (io), 84 I/O50 (io), 85 I/O51 (io), 86 GND (power), 87 I/O52 (io), 88 CLK0 (in), 89 CLK1 (in), 90 VCC (power), 91 I/O53 (io), 92 I/O54 (io), 93 I/O55 (io), 94 I/O56 (io), 95 I/O57 (io), 96 I/O58 (io), 97 GND (power), 98 I/O59 (io), 99 VCC (power), 100 I/O60 (io)

## ispLSI5256VE-80LT128I
designator U?
ispLSI 5256VE SuperWIDE High Density PLD with 96 User I/Os, 12 ns, 3.3 V, Industrial Grade
footprint TQFP128_N (Thin QFP, 128-Leads, Body 14x14mm, Pitch 0.4mm, IPC Medium Density)
footprint TQFP128_L (Thin QFP, 128-Leads, Body 14x14mm, Pitch 0.4mm, IPC High Density)
footprint TQFP128_M (Thin QFP, 128-Leads, Body 14x14mm, Pitch 0.4mm, IPC Low Density)
3D model 5256VE-TQFP128 (128-Pin Thin Quad Flat Pack 0.4 mm Pitch)
pins: 1 I/O82 (io), 2 I/O83 (io), 3 I/O84 (io), 4 I/O85 (io), 5 I/O86 (io), 6 I/O87 (io), 7 GND (power), 8 I/O88 (io), 9 VCC (power), 10 I/O89 (io), 11 I/O90 (io), 12 I/O91 (io), 13 I/O92 (io), 14 I/O93 (io), 15 I/O94 (io), 16 I/O95 (io), 17 GND (power), 18 TMS (in), 19 TCK (in), 20 TDI (in), 21 VCC (power), 22 I/O0/TOE (io), 23 I/O1 (io), 24 I/O2 (io), 25 I/O3 (io), 26 I/O4 (io), 27 GND (power), 28 I/O5 (io), 29 VCC (power), 30 I/O6 (io), 31 I/O7 (io), 32 I/O8 (io), 33 I/O9 (io), 34 I/O10 (io), 35 I/O11 (io), 36 I/O12 (io), 37 GND (power), 38 I/O13 (io), 39 I/O14 (io), 40 VCC (power), 41 I/O15 (io), 42 I/O16 (io), 43 I/O17 (io), 44 I/O18 (io), 45 I/O19 (io), 46 I/O20 (io), 47 I/O21 (io), 48 I/O22 (io), 49 I/O23 (io), 50 GND (power), 51 GOE0 (in), 52 GOE1 (in), 53 VCC (power), 54 I/O24 (io), 55 I/O25 (io), 56 I/O26 (io), 57 I/O27 (io), 58 I/O28 (io), 59 I/O29 (io), 60 I/O30 (io), 61 I/O31 (io), 62 I/O32 (io), 63 I/O33 (io), 64 I/O34 (io), 65 VCC (power), 66 I/O35 (io), 67 GND (power), 68 I/O36 (io), 69 I/O37 (io), 70 I/O38 (io), 71 I/O39 (io), 72 I/O40 (io), 73 GND (power), 74 I/O41 (io), 75 VCC (power), 76 I/O42 (io), 77 I/O43 (io), 78 I/O44 (io), 79 I/O45 (io), 80 I/O46 (io), 81 I/O47 (io), 82 GND (power), 83 TDO (out), 84 VCCIO (power), 85 RESET (in), 86 VCC (power), 87 I/O48 (io), 88 I/O49 (io), 89 I/O50 (io), 90 I/O51 (io), 91 I/O52 (io), 92 I/O53 (io), 93 I/O54 (io), 94 I/O55 (io), 95 I/O56 (io), 96 VCC (power), 97 I/O57 (io), 98 I/O58 (io), 99 I/O59/CLK2 (io), 100 GND (power), 101 I/O60 (io), 102 I/O61 (io), 103 I/O62 (io), 104 I/O63 (io), 105 I/O64 (io), 106 I/O65/CLK3 (io), 107 I/O66 (io), 108 I/O67 (io), 109 I/O68 (io), 110 GND (power), 111 I/O69 (io), 112 I/O70 (io), 113 CLK0 (in), 114 CLK1 (in), 115 VCC (power), 116 I/O71 (io), 117 I/O72 (io), 118 I/O73 (io), 119 I/O74 (io), 120 I/O75 (io), 121 I/O76 (io), 122 I/O77 (io), 123 GND (power), 124 I/O78 (io), 125 VCC (power), 126 I/O79 (io), 127 I/O80 (io), 128 I/O81 (io)

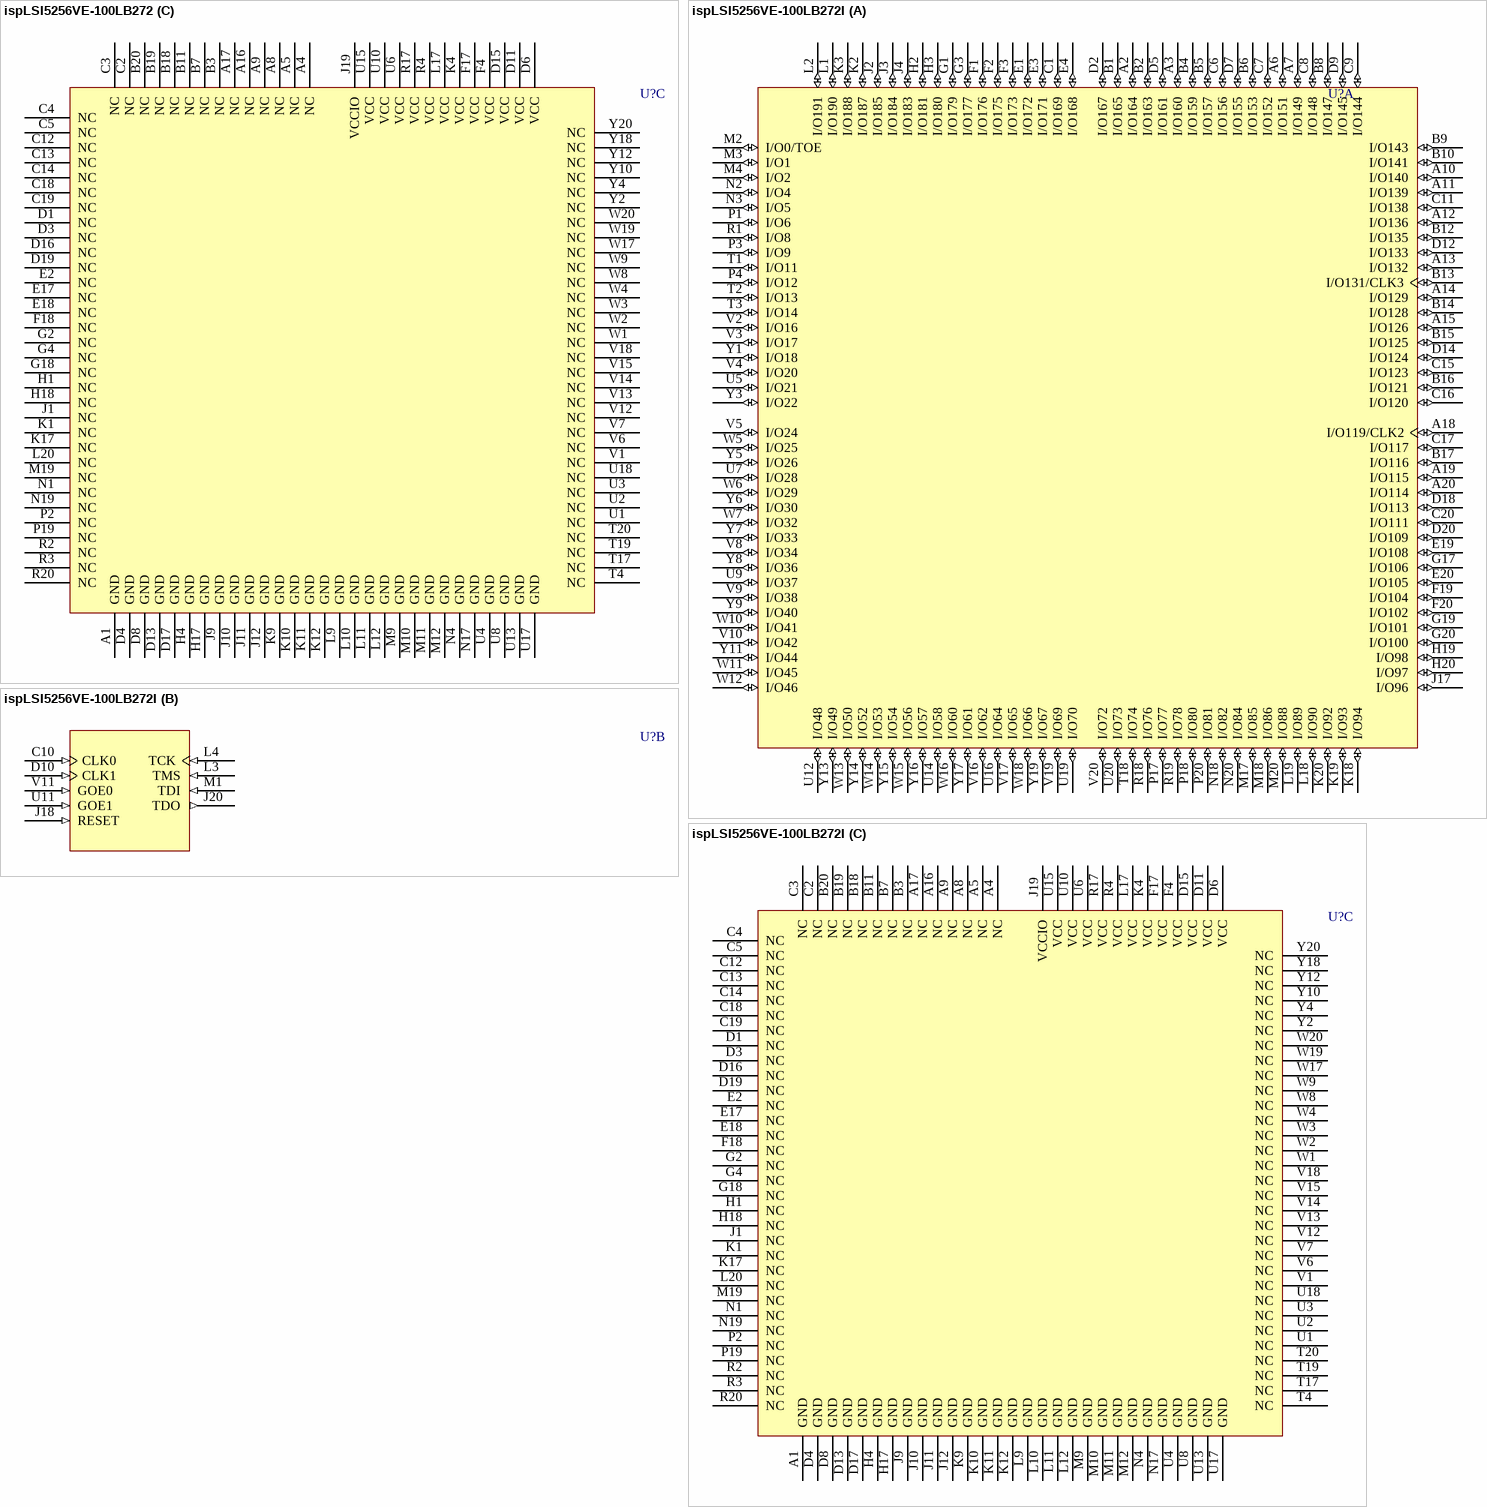
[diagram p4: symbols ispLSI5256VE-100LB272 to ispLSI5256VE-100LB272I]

## ispLSI5256VE-100LB272
designator U?
ispLSI 5256VE SuperWIDE High Density PLD with 144 User I/Os, 10 ns, 3.3 V, Commercial Grade
footprint BGA272 (BGA, 272-Leads, Body 27x27mm, Pitch 1.27mm)
3D model 5256VE-BGA272 (272-Ball Ball Grid Array (BGA272))
part A pins: A2 I/O164 (io), A3 I/O160 (io), A6 I/O151 (io), A7 I/O149 (io), A10 I/O140 (io), A11 I/O139 (io), A12 I/O136 (io), A13 I/O132 (io), A14 I/O129 (io), A15 I/O126 (io), A18 I/O119/CLK2 (io), A19 I/O115 (io), A20 I/O114 (io), B1 I/O165 (io), B2 I/O163 (io), B4 I/O159 (io), B5 I/O157 (io), B6 I/O153 (io), B8 I/O147 (io), B9 I/O143 (io), B10 I/O141 (io), B12 I/O135 (io), B13 I/O131/CLK3 (io), B14 I/O128 (io), B15 I/O125 (io), B16 I/O121 (io), B17 I/O116 (io), C1 I/O169 (io), C6 I/O156 (io), C7 I/O152 (io), C8 I/O148 (io), C9 I/O144 (io), C11 I/O138 (io), C15 I/O123 (io), C16 I/O120 (io), C17 I/O117 (io), C20 I/O111 (io), D2 I/O167 (io), D5 I/O161 (io), D7 I/O155 (io), D9 I/O145 (io), D12 I/O133 (io), D14 I/O124 (io), D18 I/O113 (io), D20 I/O109 (io), E1 I/O172 (io), E3 I/O171 (io), E4 I/O168 (io), E19 I/O108 (io), E20 I/O105 (io), F1 I/O176 (io), F2 I/O175 (io), F3 I/O173 (io), F19 I/O104 (io), F20 I/O102 (io), G1 I/O179 (io), G3 I/O177 (io), G17 I/O106 (io), G19 I/O101 (io), G20 I/O100 (io), H2 I/O181 (io), H3 I/O180 (io), H19 I/O98 (io), H20 I/O97 (io), J2 I/O185 (io), J3 I/O184 (io), J4 I/O183 (io), J17 I/O96 (io), K2 I/O187 (io), K3 I/O188 (io), K18 I/O94 (io), K19 I/O93 (io), K20 I/O92 (io), L1 I/O190 (io), L2 I/O191 (io), L18 I/O90 (io), L19 I/O89 (io), M2 I/O0/TOE (io), M3 I/O1 (io), M4 I/O2 (io), M17 I/O85 (io), M18 I/O86 (io), M20 I/O88 (io), N2 I/O4 (io), N3 I/O5 (io), N18 I/O82 (io), N20 I/O84 (io), P1 I/O6 (io), P3 I/O9 (io), P4 I/O12 (io), P17 I/O77 (io), P18 I/O80 (io), P20 I/O81 (io), R1 I/O8 (io), R18 I/O76 (io), R19 I/O78 (io), T1 I/O11 (io), T2 I/O13 (io), T3 I/O14 (io), T18 I/O74 (io), U5 I/O21 (io), U7 I/O28 (io), U9 I/O37 (io), U12 I/O48 (io), U14 I/O58 (io), U16 I/O64 (io), U19 I/O70 (io), U20 I/O73 (io), V2 I/O16 (io), V3 I/O17 (io), V4 I/O20 (io), V5 I/O24 (io), V8 I/O34 (io), V9 I/O38 (io), V10 I/O42 (io), V16 I/O62 (io), V17 I/O65 (io), V19 I/O69 (io), V20 I/O72 (io), W5 I/O25 (io), W6 I/O29 (io), W7 I/O32 (io), W10 I/O41 (io), W11 I/O45 (io), W12 I/O46 (io), W13 I/O50 (io), W14 I/O53 (io), W15 I/O56 (io), W16 I/O60 (io), W18 I/O66 (io), Y1 I/O18 (io), Y3 I/O22 (io), Y5 I/O26 (io), Y6 I/O30 (io), Y7 I/O33 (io), Y8 I/O36 (io), Y9 I/O40 (io), Y11 I/O44 (io), Y13 I/O49 (io), Y14 I/O52 (io), Y15 I/O54 (io), Y16 I/O57 (io), Y17 I/O61 (io), Y19 I/O67 (io)
part B pins: C10 CLK0 (in), D10 CLK1 (in), J18 RESET (in), J20 TDO (out), L3 TMS (in), L4 TCK (in), M1 TDI (in), U11 GOE1 (in), V11 GOE0 (in)
part C pins: A1 GND (power), A4 NC, A5 NC, A8 NC, A9 NC, A16 NC, A17 NC, B3 NC, B7 NC, B11 NC, B18 NC, B19 NC, B20 NC, C2 NC, C3 NC, C4 NC, C5 NC, C12 NC, C13 NC, C14 NC, C18 NC, C19 NC, D1 NC, D3 NC, D4 GND (power), D6 VCC (power), D8 GND (power), D11 VCC (power), D13 GND (power), D15 VCC (power), D16 NC, D17 GND (power), D19 NC, E2 NC, E17 NC, E18 NC, F4 VCC (power), F17 VCC (power), F18 NC, G2 NC, G4 NC, G18 NC, H1 NC, H4 GND (power), H17 GND (power), H18 NC, J1 NC, J9 GND (power), J10 GND (power), J11 GND (power), J12 GND (power), J19 VCCIO (power), K1 NC, K4 VCC (power), K9 GND (power), K10 GND (power), K11 GND (power), K12 GND (power), K17 NC, L9 GND (power), L10 GND (power), L11 GND (power), L12 GND (power), L17 VCC (power), L20 NC, M9 GND (power), M10 GND (power), M11 GND (power), M12 GND (power), M19 NC, N1 NC, N4 GND (power), N17 GND (power), N19 NC, P2 NC, P19 NC, R2 NC, R3 NC, R4 VCC (power), R17 VCC (power), R20 NC, T4 NC, T17 NC, T19 NC, T20 NC, U1 NC, U2 NC, U3 NC, U4 GND (power), U6 VCC (power), U8 GND (power), U10 VCC (power), U13 GND (power), U15 VCC (power), U17 GND (power), U18 NC, V1 NC, V6 NC, V7 NC, V12 NC, V13 NC, V14 NC, V15 NC, V18 NC, W1 NC, W2 NC, W3 NC, W4 NC, W8 NC, W9 NC, W17 NC, W19 NC, W20 NC, Y2 NC, Y4 NC, Y10 NC, Y12 NC, Y18 NC, Y20 NC

## ispLSI5256VE-100LB272I
designator U?
ispLSI 5256VE SuperWIDE High Density PLD with 144 User I/Os, 10 ns, 3.3 V, Industrial Grade
footprint BGA272 (BGA, 272-Leads, Body 27x27mm, Pitch 1.27mm)
3D model 5256VE-BGA272 (272-Ball Ball Grid Array (BGA272))
part A pins: A2 I/O164 (io), A3 I/O160 (io), A6 I/O151 (io), A7 I/O149 (io), A10 I/O140 (io), A11 I/O139 (io), A12 I/O136 (io), A13 I/O132 (io), A14 I/O129 (io), A15 I/O126 (io), A18 I/O119/CLK2 (io), A19 I/O115 (io), A20 I/O114 (io), B1 I/O165 (io), B2 I/O163 (io), B4 I/O159 (io), B5 I/O157 (io), B6 I/O153 (io), B8 I/O147 (io), B9 I/O143 (io), B10 I/O141 (io), B12 I/O135 (io), B13 I/O131/CLK3 (io), B14 I/O128 (io), B15 I/O125 (io), B16 I/O121 (io), B17 I/O116 (io), C1 I/O169 (io), C6 I/O156 (io), C7 I/O152 (io), C8 I/O148 (io), C9 I/O144 (io), C11 I/O138 (io), C15 I/O123 (io), C16 I/O120 (io), C17 I/O117 (io), C20 I/O111 (io), D2 I/O167 (io), D5 I/O161 (io), D7 I/O155 (io), D9 I/O145 (io), D12 I/O133 (io), D14 I/O124 (io), D18 I/O113 (io), D20 I/O109 (io), E1 I/O172 (io), E3 I/O171 (io), E4 I/O168 (io), E19 I/O108 (io), E20 I/O105 (io), F1 I/O176 (io), F2 I/O175 (io), F3 I/O173 (io), F19 I/O104 (io), F20 I/O102 (io), G1 I/O179 (io), G3 I/O177 (io), G17 I/O106 (io), G19 I/O101 (io), G20 I/O100 (io), H2 I/O181 (io), H3 I/O180 (io), H19 I/O98 (io), H20 I/O97 (io), J2 I/O185 (io), J3 I/O184 (io), J4 I/O183 (io), J17 I/O96 (io), K2 I/O187 (io), K3 I/O188 (io), K18 I/O94 (io), K19 I/O93 (io), K20 I/O92 (io), L1 I/O190 (io), L2 I/O191 (io), L18 I/O90 (io), L19 I/O89 (io), M2 I/O0/TOE (io), M3 I/O1 (io), M4 I/O2 (io), M17 I/O85 (io), M18 I/O86 (io), M20 I/O88 (io), N2 I/O4 (io), N3 I/O5 (io), N18 I/O82 (io), N20 I/O84 (io), P1 I/O6 (io), P3 I/O9 (io), P4 I/O12 (io), P17 I/O77 (io), P18 I/O80 (io), P20 I/O81 (io), R1 I/O8 (io), R18 I/O76 (io), R19 I/O78 (io), T1 I/O11 (io), T2 I/O13 (io), T3 I/O14 (io), T18 I/O74 (io), U5 I/O21 (io), U7 I/O28 (io), U9 I/O37 (io), U12 I/O48 (io), U14 I/O58 (io), U16 I/O64 (io), U19 I/O70 (io), U20 I/O73 (io), V2 I/O16 (io), V3 I/O17 (io), V4 I/O20 (io), V5 I/O24 (io), V8 I/O34 (io), V9 I/O38 (io), V10 I/O42 (io), V16 I/O62 (io), V17 I/O65 (io), V19 I/O69 (io), V20 I/O72 (io), W5 I/O25 (io), W6 I/O29 (io), W7 I/O32 (io), W10 I/O41 (io), W11 I/O45 (io), W12 I/O46 (io), W13 I/O50 (io), W14 I/O53 (io), W15 I/O56 (io), W16 I/O60 (io), W18 I/O66 (io), Y1 I/O18 (io), Y3 I/O22 (io), Y5 I/O26 (io), Y6 I/O30 (io), Y7 I/O33 (io), Y8 I/O36 (io), Y9 I/O40 (io), Y11 I/O44 (io), Y13 I/O49 (io), Y14 I/O52 (io), Y15 I/O54 (io), Y16 I/O57 (io), Y17 I/O61 (io), Y19 I/O67 (io)
part B pins: C10 CLK0 (in), D10 CLK1 (in), J18 RESET (in), J20 TDO (out), L3 TMS (in), L4 TCK (in), M1 TDI (in), U11 GOE1 (in), V11 GOE0 (in)
part C pins: A1 GND (power), A4 NC, A5 NC, A8 NC, A9 NC, A16 NC, A17 NC, B3 NC, B7 NC, B11 NC, B18 NC, B19 NC, B20 NC, C2 NC, C3 NC, C4 NC, C5 NC, C12 NC, C13 NC, C14 NC, C18 NC, C19 NC, D1 NC, D3 NC, D4 GND (power), D6 VCC (power), D8 GND (power), D11 VCC (power), D13 GND (power), D15 VCC (power), D16 NC, D17 GND (power), D19 NC, E2 NC, E17 NC, E18 NC, F4 VCC (power), F17 VCC (power), F18 NC, G2 NC, G4 NC, G18 NC, H1 NC, H4 GND (power), H17 GND (power), H18 NC, J1 NC, J9 GND (power), J10 GND (power), J11 GND (power), J12 GND (power), J19 VCCIO (power), K1 NC, K4 VCC (power), K9 GND (power), K10 GND (power), K11 GND (power), K12 GND (power), K17 NC, L9 GND (power), L10 GND (power), L11 GND (power), L12 GND (power), L17 VCC (power), L20 NC, M9 GND (power), M10 GND (power), M11 GND (power), M12 GND (power), M19 NC, N1 NC, N4 GND (power), N17 GND (power), N19 NC, P2 NC, P19 NC, R2 NC, R3 NC, R4 VCC (power), R17 VCC (power), R20 NC, T4 NC, T17 NC, T19 NC, T20 NC, U1 NC, U2 NC, U3 NC, U4 GND (power), U6 VCC (power), U8 GND (power), U10 VCC (power), U13 GND (power), U15 VCC (power), U17 GND (power), U18 NC, V1 NC, V6 NC, V7 NC, V12 NC, V13 NC, V14 NC, V15 NC, V18 NC, W1 NC, W2 NC, W3 NC, W4 NC, W8 NC, W9 NC, W17 NC, W19 NC, W20 NC, Y2 NC, Y4 NC, Y10 NC, Y12 NC, Y18 NC, Y20 NC

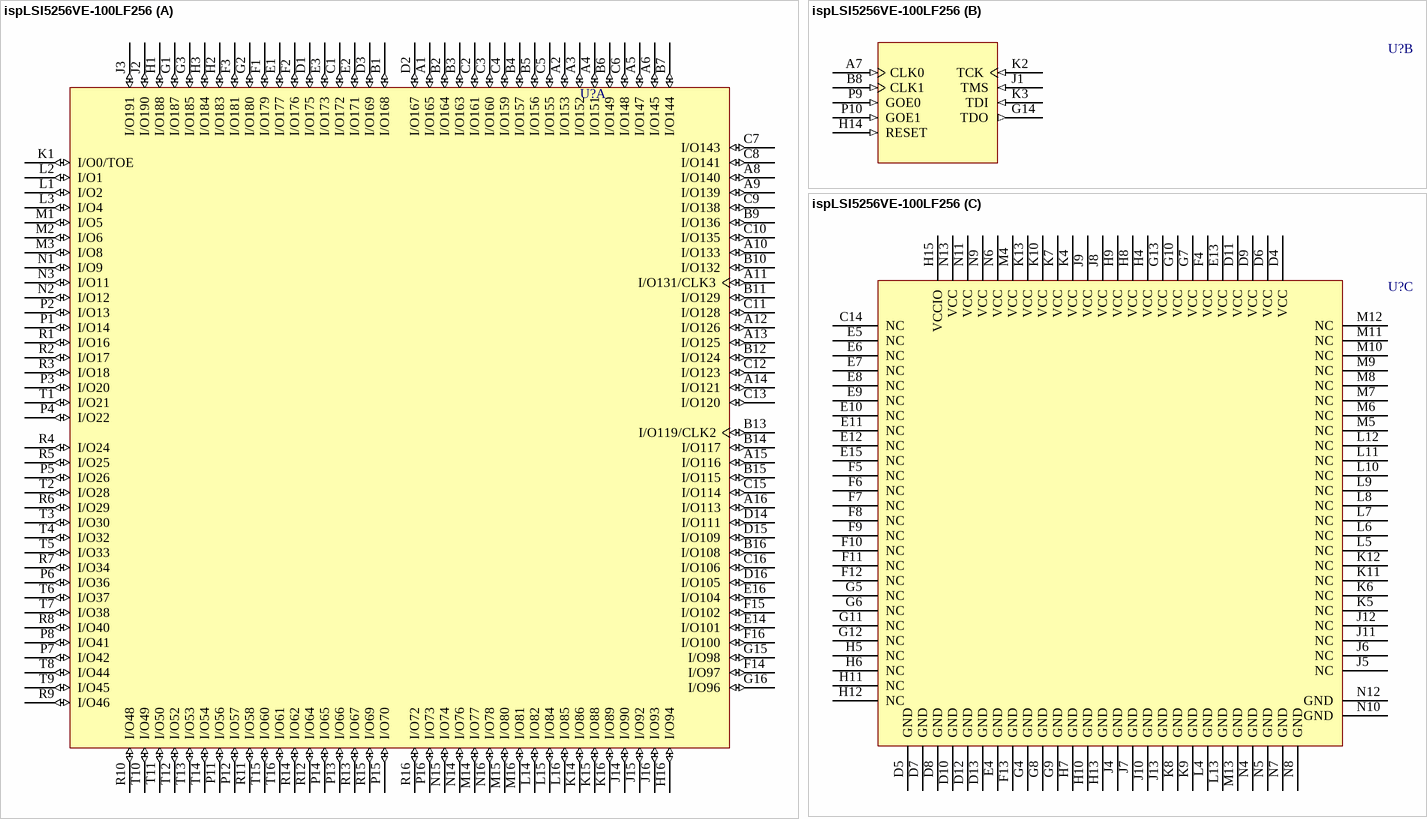
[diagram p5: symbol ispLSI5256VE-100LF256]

## ispLSI5256VE-100LF256
designator U?
ispLSI 5256VE SuperWIDE High Density PLD with 144 User I/Os, 10 ns, 3.3 V, Commercial Grade
footprint fpBGA256 (BGA, 256-Leads, Body 17x17mm, Pitch 1mm)
3D model 5256VE-fpBGA256 (256-Ball Fine Pitch Ball Grid Array (fpBGA256))
part A pins: A1 I/O165 (io), A2 I/O153 (io), A3 I/O152 (io), A4 I/O151 (io), A5 I/O147 (io), A6 I/O145 (io), A8 I/O140 (io), A9 I/O139 (io), A10 I/O133 (io), A11 I/O131/CLK3 (io), A12 I/O126 (io), A13 I/O125 (io), A14 I/O121 (io), A15 I/O116 (io), A16 I/O113 (io), B1 I/O168 (io), B2 I/O164 (io), B3 I/O163 (io), B4 I/O157 (io), B5 I/O156 (io), B6 I/O149 (io), B7 I/O144 (io), B9 I/O136 (io), B10 I/O132 (io), B11 I/O129 (io), B12 I/O124 (io), B13 I/O119/CLK2 (io), B14 I/O117 (io), B15 I/O115 (io), B16 I/O108 (io), C1 I/O172 (io), C2 I/O161 (io), C3 I/O160 (io), C4 I/O159 (io), C5 I/O155 (io), C6 I/O148 (io), C7 I/O143 (io), C8 I/O141 (io), C9 I/O138 (io), C10 I/O135 (io), C11 I/O128 (io), C12 I/O123 (io), C13 I/O120 (io), C15 I/O114 (io), C16 I/O106 (io), D1 I/O175 (io), D2 I/O167 (io), D3 I/O169 (io), D14 I/O111 (io), D15 I/O109 (io), D16 I/O105 (io), E1 I/O177 (io), E2 I/O171 (io), E3 I/O173 (io), E14 I/O101 (io), E16 I/O104 (io), F1 I/O179 (io), F2 I/O176 (io), F3 I/O181 (io), F14 I/O97 (io), F15 I/O102 (io), F16 I/O100 (io), G1 I/O187 (io), G2 I/O180 (io), G3 I/O185 (io), G15 I/O98 (io), G16 I/O96 (io), H1 I/O188 (io), H2 I/O183 (io), H3 I/O184 (io), H16 I/O94 (io), J2 I/O190 (io), J3 I/O191 (io), J14 I/O90 (io), J15 I/O92 (io), J16 I/O93 (io), K1 I/O0/TOE (io), K14 I/O86 (io), K15 I/O88 (io), K16 I/O89 (io), L1 I/O2 (io), L2 I/O1 (io), L3 I/O4 (io), L14 I/O82 (io), L15 I/O84 (io), L16 I/O85 (io), M1 I/O5 (io), M2 I/O6 (io), M3 I/O8 (io), M14 I/O77 (io), M15 I/O80 (io), M16 I/O81 (io), N1 I/O9 (io), N2 I/O12 (io), N3 I/O11 (io), N14 I/O76 (io), N15 I/O74 (io), N16 I/O78 (io), P1 I/O14 (io), P2 I/O13 (io), P3 I/O20 (io), P4 I/O22 (io), P5 I/O26 (io), P6 I/O36 (io), P7 I/O42 (io), P8 I/O41 (io), P11 I/O56 (io), P12 I/O57 (io), P13 I/O66 (io), P14 I/O65 (io), P15 I/O70 (io), P16 I/O73 (io), R1 I/O16 (io), R2 I/O17 (io), R3 I/O18 (io), R4 I/O24 (io), R5 I/O25 (io), R6 I/O29 (io), R7 I/O34 (io), R8 I/O40 (io), R9 I/O46 (io), R10 I/O48 (io), R11 I/O58 (io), R12 I/O64 (io), R13 I/O67 (io), R14 I/O62 (io), R15 I/O69 (io), R16 I/O72 (io), T1 I/O21 (io), T2 I/O28 (io), T3 I/O30 (io), T4 I/O32 (io), T5 I/O33 (io), T6 I/O37 (io), T7 I/O38 (io), T8 I/O44 (io), T9 I/O45 (io), T10 I/O49 (io), T11 I/O50 (io), T12 I/O52 (io), T13 I/O53 (io), T14 I/O54 (io), T15 I/O60 (io), T16 I/O61 (io)
part B pins: A7 CLK0 (in), B8 CLK1 (in), G14 TDO (out), H14 RESET (in), J1 TMS (in), K2 TCK (in), K3 TDI (in), P9 GOE0 (in), P10 GOE1 (in)
part C pins: C14 NC, D4 VCC (power), D5 GND (power), D6 VCC (power), D7 GND (power), D8 GND (power), D9 VCC (power), D10 GND (power), D11 VCC (power), D12 GND (power), D13 GND (power), E4 GND (power), E5 NC, E6 NC, E7 NC, E8 NC, E9 NC, E10 NC, E11 NC, E12 NC, E13 VCC (power), E15 NC, F4 VCC (power), F5 NC, F6 NC, F7 NC, F8 NC, F9 NC, F10 NC, F11 NC, F12 NC, F13 GND (power), G4 GND (power), G5 NC, G6 NC, G7 VCC (power), G8 GND (power), G9 GND (power), G10 VCC (power), G11 NC, G12 NC, G13 VCC (power), H4 VCC (power), H5 NC, H6 NC, H7 GND (power), H8 VCC (power), H9 VCC (power), H10 GND (power), H11 NC, H12 NC, H13 GND (power), H15 VCCIO (power), J4 GND (power), J5 NC, J6 NC, J7 GND (power), J8 VCC (power), J9 VCC (power), J10 GND (power), J11 NC, J12 NC, J13 GND (power), K4 VCC (power), K5 NC, K6 NC, K7 VCC (power), K8 GND (power), K9 GND (power), K10 VCC (power), K11 NC, K12 NC, K13 VCC (power), L4 GND (power), L5 NC, L6 NC, L7 NC, L8 NC, L9 NC, L10 NC, L11 NC, L12 NC, L13 GND (power), M4 VCC (power), M5 NC, M6 NC, M7 NC, M8 NC, M9 NC, M10 NC, M11 NC, M12 NC, M13 GND (power), N4 GND (power), N5 GND (power), N6 VCC (power), N7 GND (power), N8 GND (power), N9 VCC (power), N10 GND (power), N11 VCC (power), N12 GND (power), N13 VCC (power)

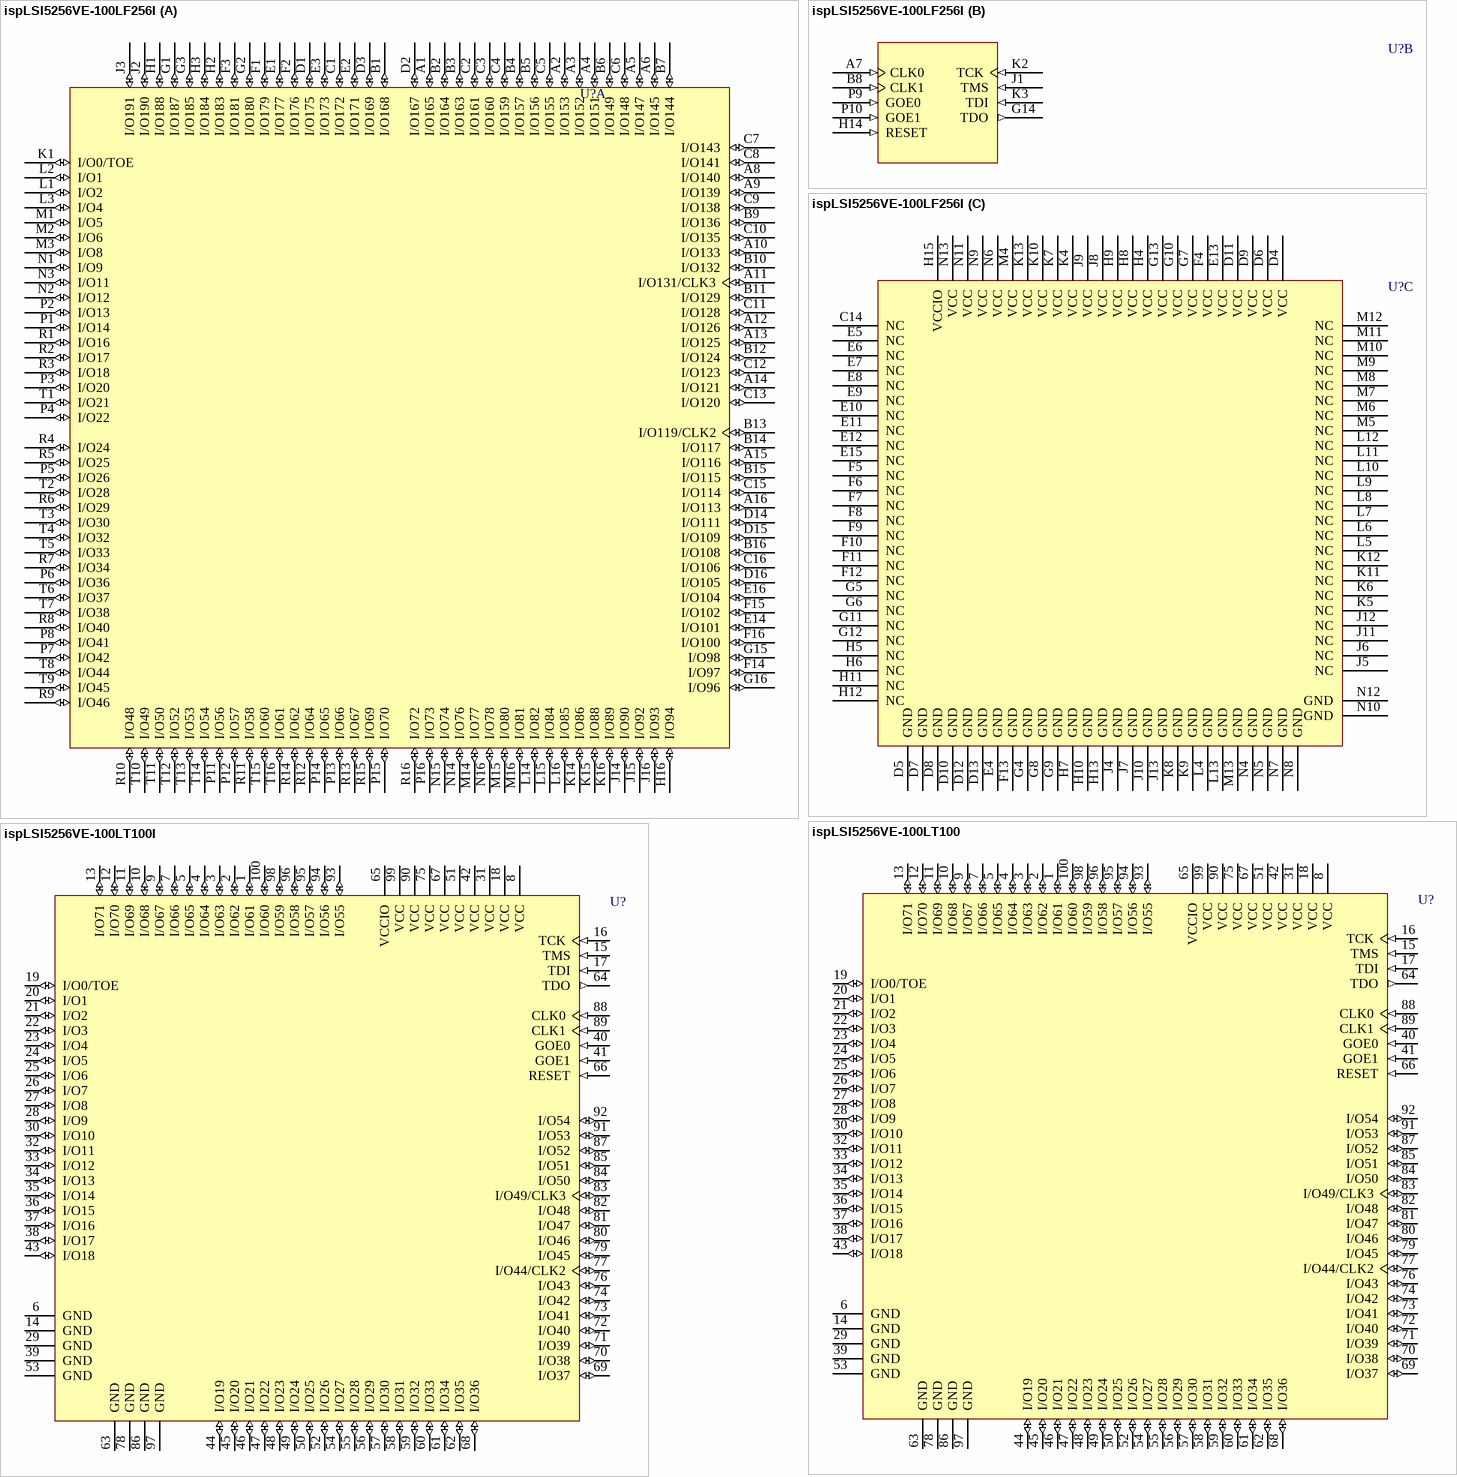
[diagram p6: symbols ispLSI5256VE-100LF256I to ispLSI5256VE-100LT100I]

## ispLSI5256VE-100LF256I
designator U?
ispLSI 5256VE SuperWIDE High Density PLD with 144 User I/Os, 10 ns, 3.3 V, Industrial Grade
footprint fpBGA256 (BGA, 256-Leads, Body 17x17mm, Pitch 1mm)
3D model 5256VE-fpBGA256 (256-Ball Fine Pitch Ball Grid Array (fpBGA256))
part A pins: A1 I/O165 (io), A2 I/O153 (io), A3 I/O152 (io), A4 I/O151 (io), A5 I/O147 (io), A6 I/O145 (io), A8 I/O140 (io), A9 I/O139 (io), A10 I/O133 (io), A11 I/O131/CLK3 (io), A12 I/O126 (io), A13 I/O125 (io), A14 I/O121 (io), A15 I/O116 (io), A16 I/O113 (io), B1 I/O168 (io), B2 I/O164 (io), B3 I/O163 (io), B4 I/O157 (io), B5 I/O156 (io), B6 I/O149 (io), B7 I/O144 (io), B9 I/O136 (io), B10 I/O132 (io), B11 I/O129 (io), B12 I/O124 (io), B13 I/O119/CLK2 (io), B14 I/O117 (io), B15 I/O115 (io), B16 I/O108 (io), C1 I/O172 (io), C2 I/O161 (io), C3 I/O160 (io), C4 I/O159 (io), C5 I/O155 (io), C6 I/O148 (io), C7 I/O143 (io), C8 I/O141 (io), C9 I/O138 (io), C10 I/O135 (io), C11 I/O128 (io), C12 I/O123 (io), C13 I/O120 (io), C15 I/O114 (io), C16 I/O106 (io), D1 I/O175 (io), D2 I/O167 (io), D3 I/O169 (io), D14 I/O111 (io), D15 I/O109 (io), D16 I/O105 (io), E1 I/O177 (io), E2 I/O171 (io), E3 I/O173 (io), E14 I/O101 (io), E16 I/O104 (io), F1 I/O179 (io), F2 I/O176 (io), F3 I/O181 (io), F14 I/O97 (io), F15 I/O102 (io), F16 I/O100 (io), G1 I/O187 (io), G2 I/O180 (io), G3 I/O185 (io), G15 I/O98 (io), G16 I/O96 (io), H1 I/O188 (io), H2 I/O183 (io), H3 I/O184 (io), H16 I/O94 (io), J2 I/O190 (io), J3 I/O191 (io), J14 I/O90 (io), J15 I/O92 (io), J16 I/O93 (io), K1 I/O0/TOE (io), K14 I/O86 (io), K15 I/O88 (io), K16 I/O89 (io), L1 I/O2 (io), L2 I/O1 (io), L3 I/O4 (io), L14 I/O82 (io), L15 I/O84 (io), L16 I/O85 (io), M1 I/O5 (io), M2 I/O6 (io), M3 I/O8 (io), M14 I/O77 (io), M15 I/O80 (io), M16 I/O81 (io), N1 I/O9 (io), N2 I/O12 (io), N3 I/O11 (io), N14 I/O76 (io), N15 I/O74 (io), N16 I/O78 (io), P1 I/O14 (io), P2 I/O13 (io), P3 I/O20 (io), P4 I/O22 (io), P5 I/O26 (io), P6 I/O36 (io), P7 I/O42 (io), P8 I/O41 (io), P11 I/O56 (io), P12 I/O57 (io), P13 I/O66 (io), P14 I/O65 (io), P15 I/O70 (io), P16 I/O73 (io), R1 I/O16 (io), R2 I/O17 (io), R3 I/O18 (io), R4 I/O24 (io), R5 I/O25 (io), R6 I/O29 (io), R7 I/O34 (io), R8 I/O40 (io), R9 I/O46 (io), R10 I/O48 (io), R11 I/O58 (io), R12 I/O64 (io), R13 I/O67 (io), R14 I/O62 (io), R15 I/O69 (io), R16 I/O72 (io), T1 I/O21 (io), T2 I/O28 (io), T3 I/O30 (io), T4 I/O32 (io), T5 I/O33 (io), T6 I/O37 (io), T7 I/O38 (io), T8 I/O44 (io), T9 I/O45 (io), T10 I/O49 (io), T11 I/O50 (io), T12 I/O52 (io), T13 I/O53 (io), T14 I/O54 (io), T15 I/O60 (io), T16 I/O61 (io)
part B pins: A7 CLK0 (in), B8 CLK1 (in), G14 TDO (out), H14 RESET (in), J1 TMS (in), K2 TCK (in), K3 TDI (in), P9 GOE0 (in), P10 GOE1 (in)
part C pins: C14 NC, D4 VCC (power), D5 GND (power), D6 VCC (power), D7 GND (power), D8 GND (power), D9 VCC (power), D10 GND (power), D11 VCC (power), D12 GND (power), D13 GND (power), E4 GND (power), E5 NC, E6 NC, E7 NC, E8 NC, E9 NC, E10 NC, E11 NC, E12 NC, E13 VCC (power), E15 NC, F4 VCC (power), F5 NC, F6 NC, F7 NC, F8 NC, F9 NC, F10 NC, F11 NC, F12 NC, F13 GND (power), G4 GND (power), G5 NC, G6 NC, G7 VCC (power), G8 GND (power), G9 GND (power), G10 VCC (power), G11 NC, G12 NC, G13 VCC (power), H4 VCC (power), H5 NC, H6 NC, H7 GND (power), H8 VCC (power), H9 VCC (power), H10 GND (power), H11 NC, H12 NC, H13 GND (power), H15 VCCIO (power), J4 GND (power), J5 NC, J6 NC, J7 GND (power), J8 VCC (power), J9 VCC (power), J10 GND (power), J11 NC, J12 NC, J13 GND (power), K4 VCC (power), K5 NC, K6 NC, K7 VCC (power), K8 GND (power), K9 GND (power), K10 VCC (power), K11 NC, K12 NC, K13 VCC (power), L4 GND (power), L5 NC, L6 NC, L7 NC, L8 NC, L9 NC, L10 NC, L11 NC, L12 NC, L13 GND (power), M4 VCC (power), M5 NC, M6 NC, M7 NC, M8 NC, M9 NC, M10 NC, M11 NC, M12 NC, M13 GND (power), N4 GND (power), N5 GND (power), N6 VCC (power), N7 GND (power), N8 GND (power), N9 VCC (power), N10 GND (power), N11 VCC (power), N12 GND (power), N13 VCC (power)

## ispLSI5256VE-100LT100
designator U?
ispLSI 5256VE SuperWIDE High Density PLD with 72 User I/Os, 10 ns, 3.3 V, Commercial Grade
footprint TQFP100_N (Thin QFP, 100-Leads, Body 14x14mm, Pitch 0.5mm, IPC Medium Density)
footprint TQFP100_L (Thin QFP, 100-Leads, Body 14x14mm, Pitch 0.5mm, IPC High Density)
footprint TQFP100_M (Thin QFP, 100-Leads, Body 14x14mm, Pitch 0.5mm, IPC Low Density)
3D model 5256VE-TQFP100 (100-Pin Thin Quad Flat Pack (TQFP100))
pins: 1 I/O61 (io), 2 I/O62 (io), 3 I/O63 (io), 4 I/O64 (io), 5 I/O65 (io), 6 GND (power), 7 I/O66 (io), 8 VCC (power), 9 I/O67 (io), 10 I/O68 (io), 11 I/O69 (io), 12 I/O70 (io), 13 I/O71 (io), 14 GND (power), 15 TMS (in), 16 TCK (in), 17 TDI (in), 18 VCC (power), 19 I/O0/TOE (io), 20 I/O1 (io), 21 I/O2 (io), 22 I/O3 (io), 23 I/O4 (io), 24 I/O5 (io), 25 I/O6 (io), 26 I/O7 (io), 27 I/O8 (io), 28 I/O9 (io), 29 GND (power), 30 I/O10 (io), 31 VCC (power), 32 I/O11 (io), 33 I/O12 (io), 34 I/O13 (io), 35 I/O14 (io), 36 I/O15 (io), 37 I/O16 (io), 38 I/O17 (io), 39 GND (power), 40 GOE0 (in), 41 GOE1 (in), 42 VCC (power), 43 I/O18 (io), 44 I/O19 (io), 45 I/O20 (io), 46 I/O21 (io), 47 I/O22 (io), 48 I/O23 (io), 49 I/O24 (io), 50 I/O25 (io), 51 VCC (power), 52 I/O26 (io), 53 GND (power), 54 I/O27 (io), 55 I/O28 (io), 56 I/O29 (io), 57 I/O30 (io), 58 I/O31 (io), 59 I/O32 (io), 60 I/O33 (io), 61 I/O34 (io), 62 I/O35 (io), 63 GND (power), 64 TDO (out), 65 VCCIO (power), 66 RESET (in), 67 VCC (power), 68 I/O36 (io), 69 I/O37 (io), 70 I/O38 (io), 71 I/O39 (io), 72 I/O40 (io), 73 I/O41 (io), 74 I/O42 (io), 75 VCC (power), 76 I/O43 (io), 77 I/O44/CLK2 (io), 78 GND (power), 79 I/O45 (io), 80 I/O46 (io), 81 I/O47 (io), 82 I/O48 (io), 83 I/O49/CLK3 (io), 84 I/O50 (io), 85 I/O51 (io), 86 GND (power), 87 I/O52 (io), 88 CLK0 (in), 89 CLK1 (in), 90 VCC (power), 91 I/O53 (io), 92 I/O54 (io), 93 I/O55 (io), 94 I/O56 (io), 95 I/O57 (io), 96 I/O58 (io), 97 GND (power), 98 I/O59 (io), 99 VCC (power), 100 I/O60 (io)

## ispLSI5256VE-100LT100I
designator U?
ispLSI 5256VE SuperWIDE High Density PLD with 72 User I/Os, 10 ns, 3.3 V, Industrial Grade
footprint TQFP100_N (Thin QFP, 100-Leads, Body 14x14mm, Pitch 0.5mm, IPC Medium Density)
footprint TQFP100_L (Thin QFP, 100-Leads, Body 14x14mm, Pitch 0.5mm, IPC High Density)
footprint TQFP100_M (Thin QFP, 100-Leads, Body 14x14mm, Pitch 0.5mm, IPC Low Density)
3D model 5256VE-TQFP100 (100-Pin Thin Quad Flat Pack (TQFP100))
pins: 1 I/O61 (io), 2 I/O62 (io), 3 I/O63 (io), 4 I/O64 (io), 5 I/O65 (io), 6 GND (power), 7 I/O66 (io), 8 VCC (power), 9 I/O67 (io), 10 I/O68 (io), 11 I/O69 (io), 12 I/O70 (io), 13 I/O71 (io), 14 GND (power), 15 TMS (in), 16 TCK (in), 17 TDI (in), 18 VCC (power), 19 I/O0/TOE (io), 20 I/O1 (io), 21 I/O2 (io), 22 I/O3 (io), 23 I/O4 (io), 24 I/O5 (io), 25 I/O6 (io), 26 I/O7 (io), 27 I/O8 (io), 28 I/O9 (io), 29 GND (power), 30 I/O10 (io), 31 VCC (power), 32 I/O11 (io), 33 I/O12 (io), 34 I/O13 (io), 35 I/O14 (io), 36 I/O15 (io), 37 I/O16 (io), 38 I/O17 (io), 39 GND (power), 40 GOE0 (in), 41 GOE1 (in), 42 VCC (power), 43 I/O18 (io), 44 I/O19 (io), 45 I/O20 (io), 46 I/O21 (io), 47 I/O22 (io), 48 I/O23 (io), 49 I/O24 (io), 50 I/O25 (io), 51 VCC (power), 52 I/O26 (io), 53 GND (power), 54 I/O27 (io), 55 I/O28 (io), 56 I/O29 (io), 57 I/O30 (io), 58 I/O31 (io), 59 I/O32 (io), 60 I/O33 (io), 61 I/O34 (io), 62 I/O35 (io), 63 GND (power), 64 TDO (out), 65 VCCIO (power), 66 RESET (in), 67 VCC (power), 68 I/O36 (io), 69 I/O37 (io), 70 I/O38 (io), 71 I/O39 (io), 72 I/O40 (io), 73 I/O41 (io), 74 I/O42 (io), 75 VCC (power), 76 I/O43 (io), 77 I/O44/CLK2 (io), 78 GND (power), 79 I/O45 (io), 80 I/O46 (io), 81 I/O47 (io), 82 I/O48 (io), 83 I/O49/CLK3 (io), 84 I/O50 (io), 85 I/O51 (io), 86 GND (power), 87 I/O52 (io), 88 CLK0 (in), 89 CLK1 (in), 90 VCC (power), 91 I/O53 (io), 92 I/O54 (io), 93 I/O55 (io), 94 I/O56 (io), 95 I/O57 (io), 96 I/O58 (io), 97 GND (power), 98 I/O59 (io), 99 VCC (power), 100 I/O60 (io)

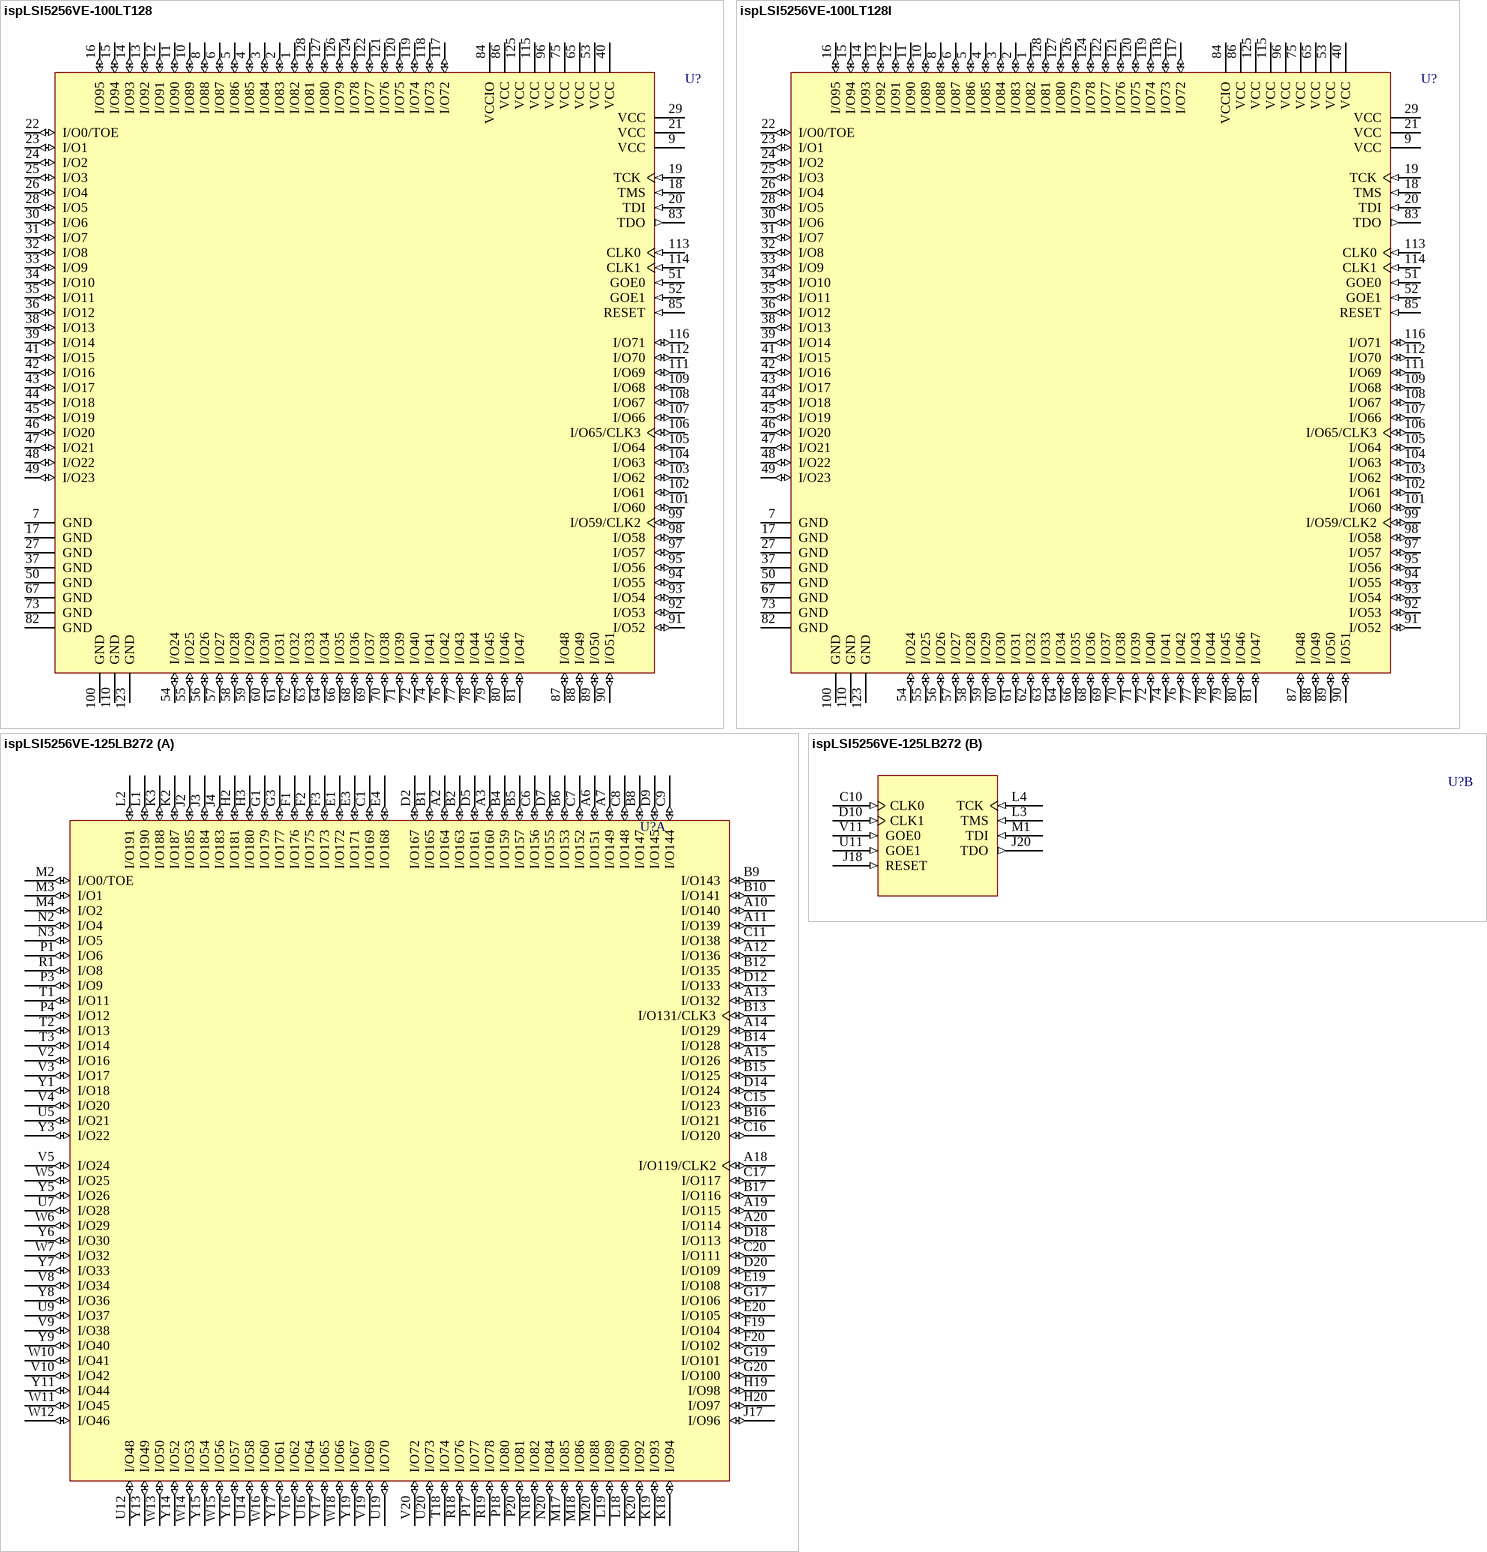
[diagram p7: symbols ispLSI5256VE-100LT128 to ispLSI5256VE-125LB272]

## ispLSI5256VE-100LT128
designator U?
ispLSI 5256VE SuperWIDE High Density PLD with 96 User I/Os, 10 ns, 3.3 V, Commercial Grade
footprint TQFP128_N (Thin QFP, 128-Leads, Body 14x14mm, Pitch 0.4mm, IPC Medium Density)
footprint TQFP128_L (Thin QFP, 128-Leads, Body 14x14mm, Pitch 0.4mm, IPC High Density)
footprint TQFP128_M (Thin QFP, 128-Leads, Body 14x14mm, Pitch 0.4mm, IPC Low Density)
3D model 5256VE-TQFP128 (128-Pin Thin Quad Flat Pack 0.4 mm Pitch)
pins: 1 I/O82 (io), 2 I/O83 (io), 3 I/O84 (io), 4 I/O85 (io), 5 I/O86 (io), 6 I/O87 (io), 7 GND (power), 8 I/O88 (io), 9 VCC (power), 10 I/O89 (io), 11 I/O90 (io), 12 I/O91 (io), 13 I/O92 (io), 14 I/O93 (io), 15 I/O94 (io), 16 I/O95 (io), 17 GND (power), 18 TMS (in), 19 TCK (in), 20 TDI (in), 21 VCC (power), 22 I/O0/TOE (io), 23 I/O1 (io), 24 I/O2 (io), 25 I/O3 (io), 26 I/O4 (io), 27 GND (power), 28 I/O5 (io), 29 VCC (power), 30 I/O6 (io), 31 I/O7 (io), 32 I/O8 (io), 33 I/O9 (io), 34 I/O10 (io), 35 I/O11 (io), 36 I/O12 (io), 37 GND (power), 38 I/O13 (io), 39 I/O14 (io), 40 VCC (power), 41 I/O15 (io), 42 I/O16 (io), 43 I/O17 (io), 44 I/O18 (io), 45 I/O19 (io), 46 I/O20 (io), 47 I/O21 (io), 48 I/O22 (io), 49 I/O23 (io), 50 GND (power), 51 GOE0 (in), 52 GOE1 (in), 53 VCC (power), 54 I/O24 (io), 55 I/O25 (io), 56 I/O26 (io), 57 I/O27 (io), 58 I/O28 (io), 59 I/O29 (io), 60 I/O30 (io), 61 I/O31 (io), 62 I/O32 (io), 63 I/O33 (io), 64 I/O34 (io), 65 VCC (power), 66 I/O35 (io), 67 GND (power), 68 I/O36 (io), 69 I/O37 (io), 70 I/O38 (io), 71 I/O39 (io), 72 I/O40 (io), 73 GND (power), 74 I/O41 (io), 75 VCC (power), 76 I/O42 (io), 77 I/O43 (io), 78 I/O44 (io), 79 I/O45 (io), 80 I/O46 (io), 81 I/O47 (io), 82 GND (power), 83 TDO (out), 84 VCCIO (power), 85 RESET (in), 86 VCC (power), 87 I/O48 (io), 88 I/O49 (io), 89 I/O50 (io), 90 I/O51 (io), 91 I/O52 (io), 92 I/O53 (io), 93 I/O54 (io), 94 I/O55 (io), 95 I/O56 (io), 96 VCC (power), 97 I/O57 (io), 98 I/O58 (io), 99 I/O59/CLK2 (io), 100 GND (power), 101 I/O60 (io), 102 I/O61 (io), 103 I/O62 (io), 104 I/O63 (io), 105 I/O64 (io), 106 I/O65/CLK3 (io), 107 I/O66 (io), 108 I/O67 (io), 109 I/O68 (io), 110 GND (power), 111 I/O69 (io), 112 I/O70 (io), 113 CLK0 (in), 114 CLK1 (in), 115 VCC (power), 116 I/O71 (io), 117 I/O72 (io), 118 I/O73 (io), 119 I/O74 (io), 120 I/O75 (io), 121 I/O76 (io), 122 I/O77 (io), 123 GND (power), 124 I/O78 (io), 125 VCC (power), 126 I/O79 (io), 127 I/O80 (io), 128 I/O81 (io)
